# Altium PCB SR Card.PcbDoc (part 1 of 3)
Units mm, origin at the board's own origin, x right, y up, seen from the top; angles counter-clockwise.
Board outline 110.01 x 84.94 mm, 10 copper layers (Top Layer, Layer 2, Layer 3, Layer 4, Layer 5, Layer 6, Layer 7, Layer 8, Layer 9, Bottom Layer), stack 2.452 mm thick; 165 components, 84 nets, 582 pads, 1965 vias.
Unrouted connection lines stored in the file: 24.
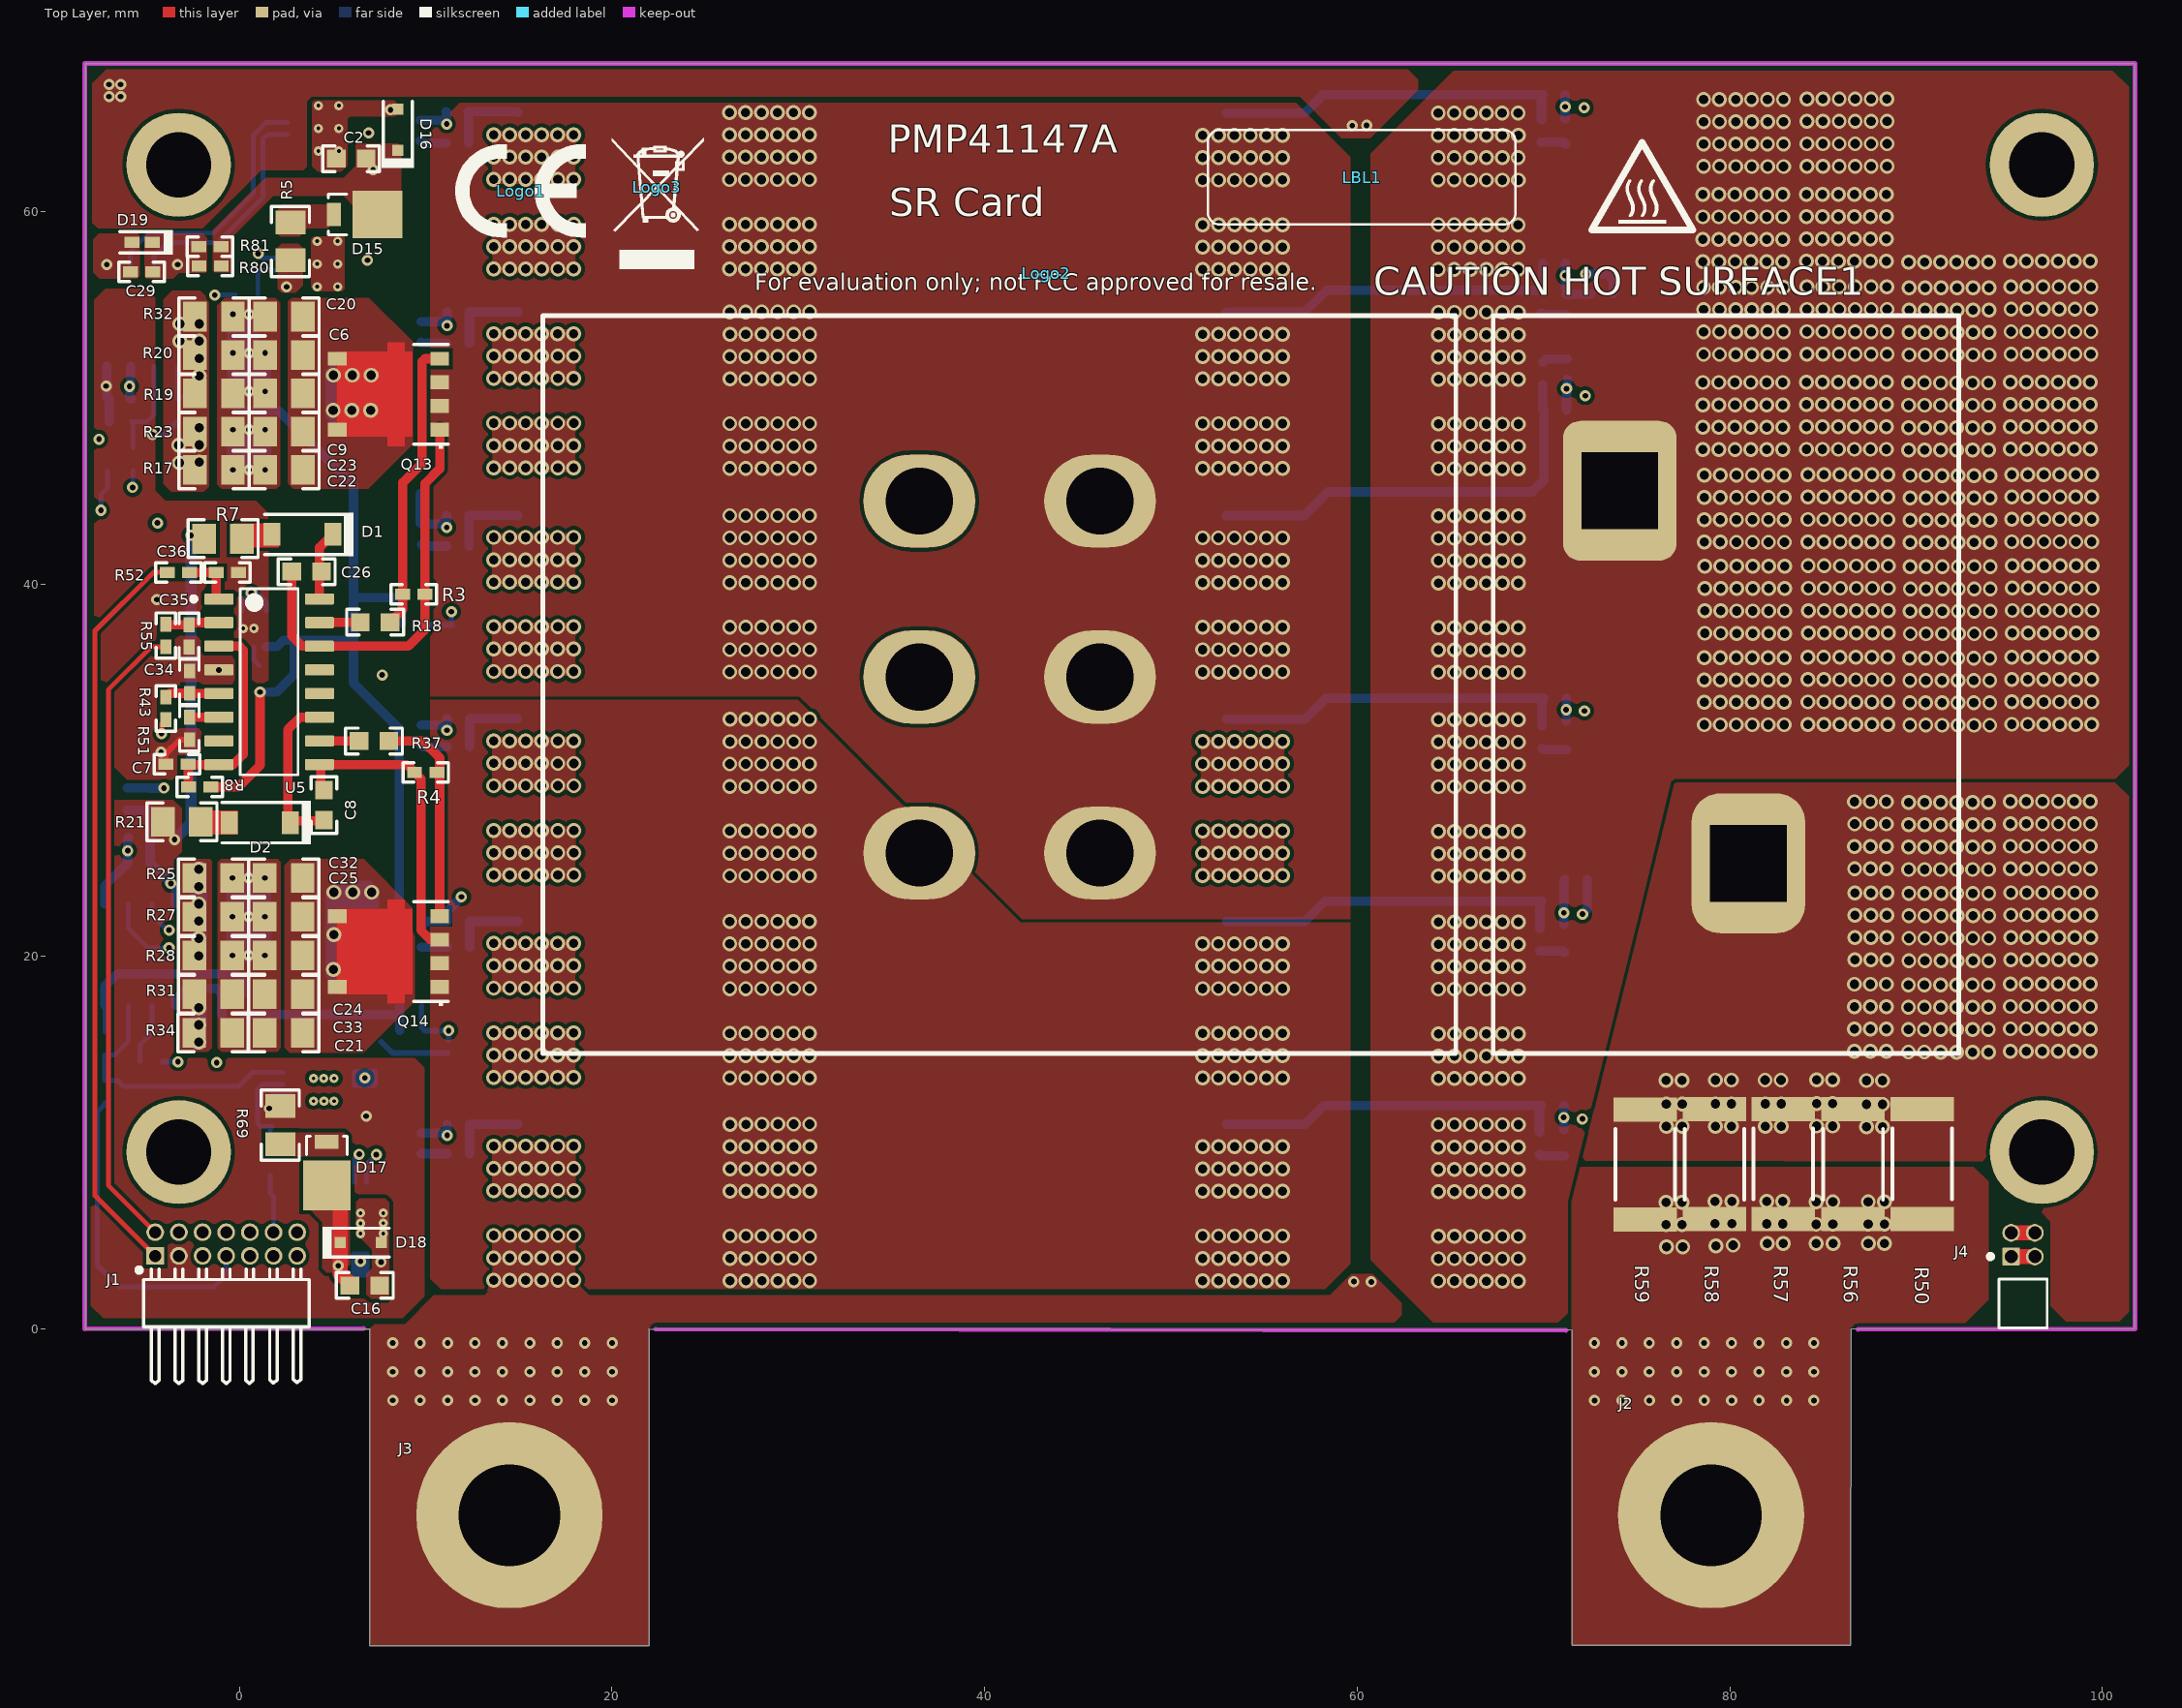
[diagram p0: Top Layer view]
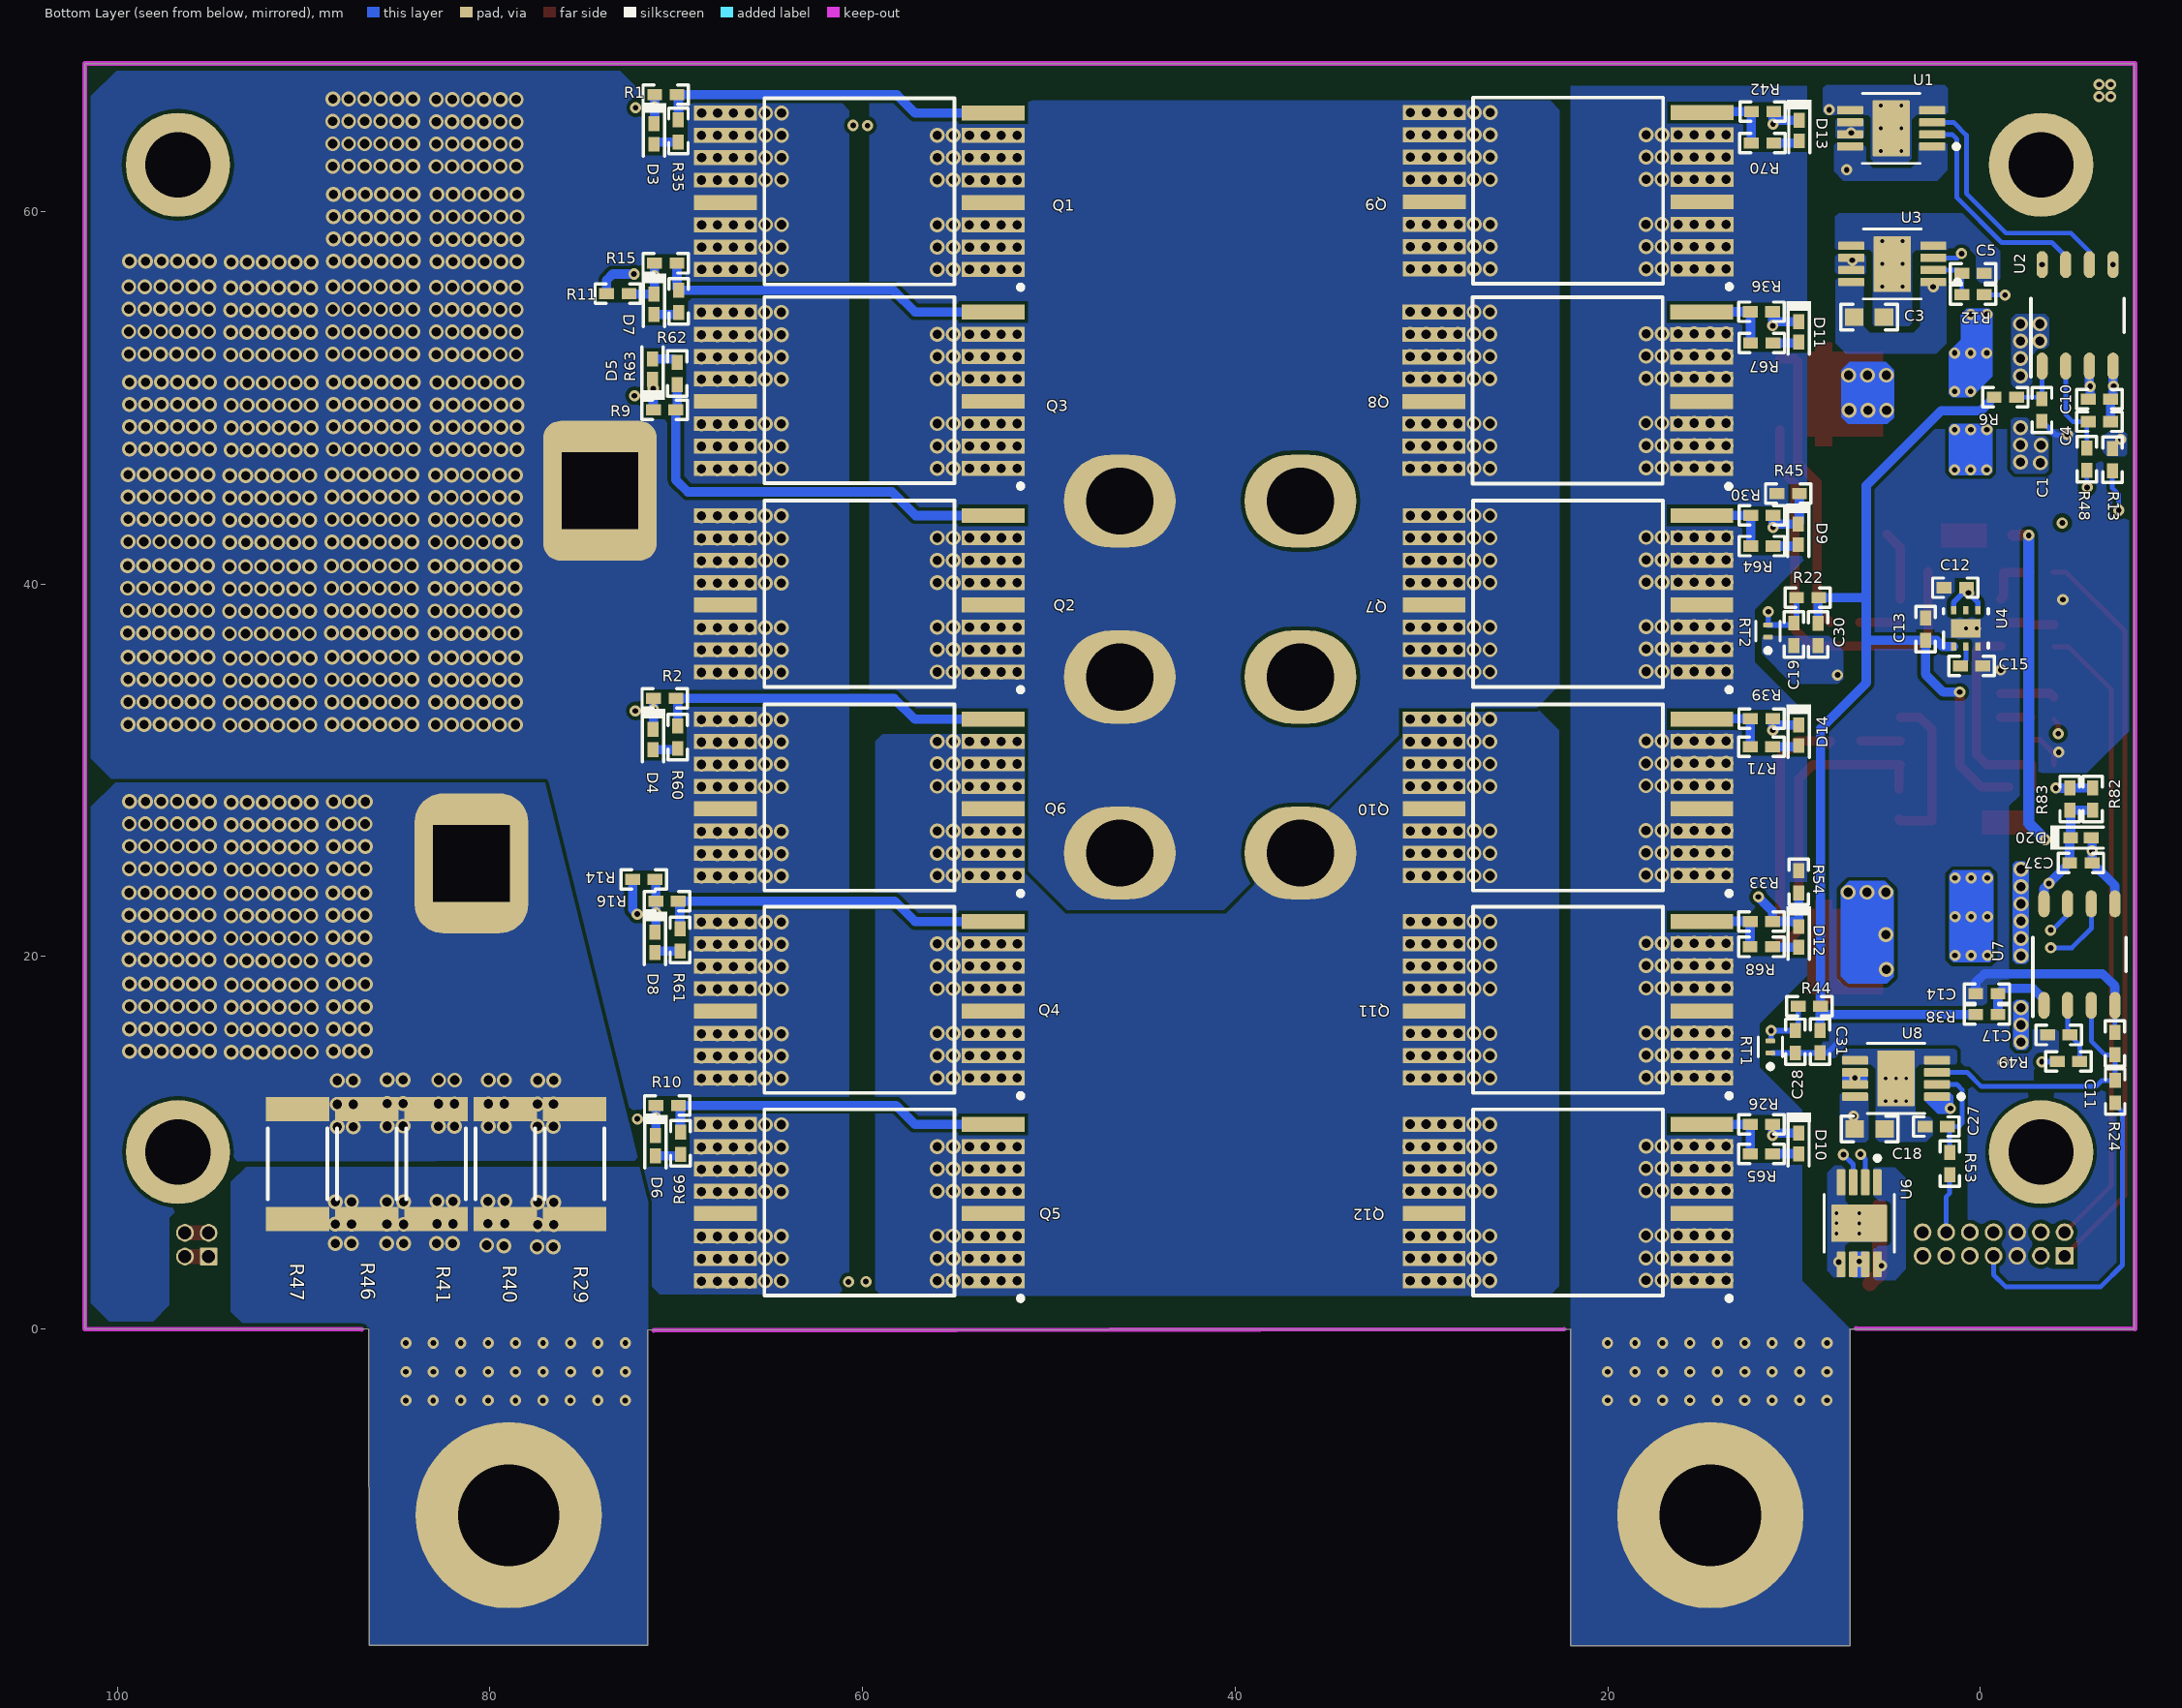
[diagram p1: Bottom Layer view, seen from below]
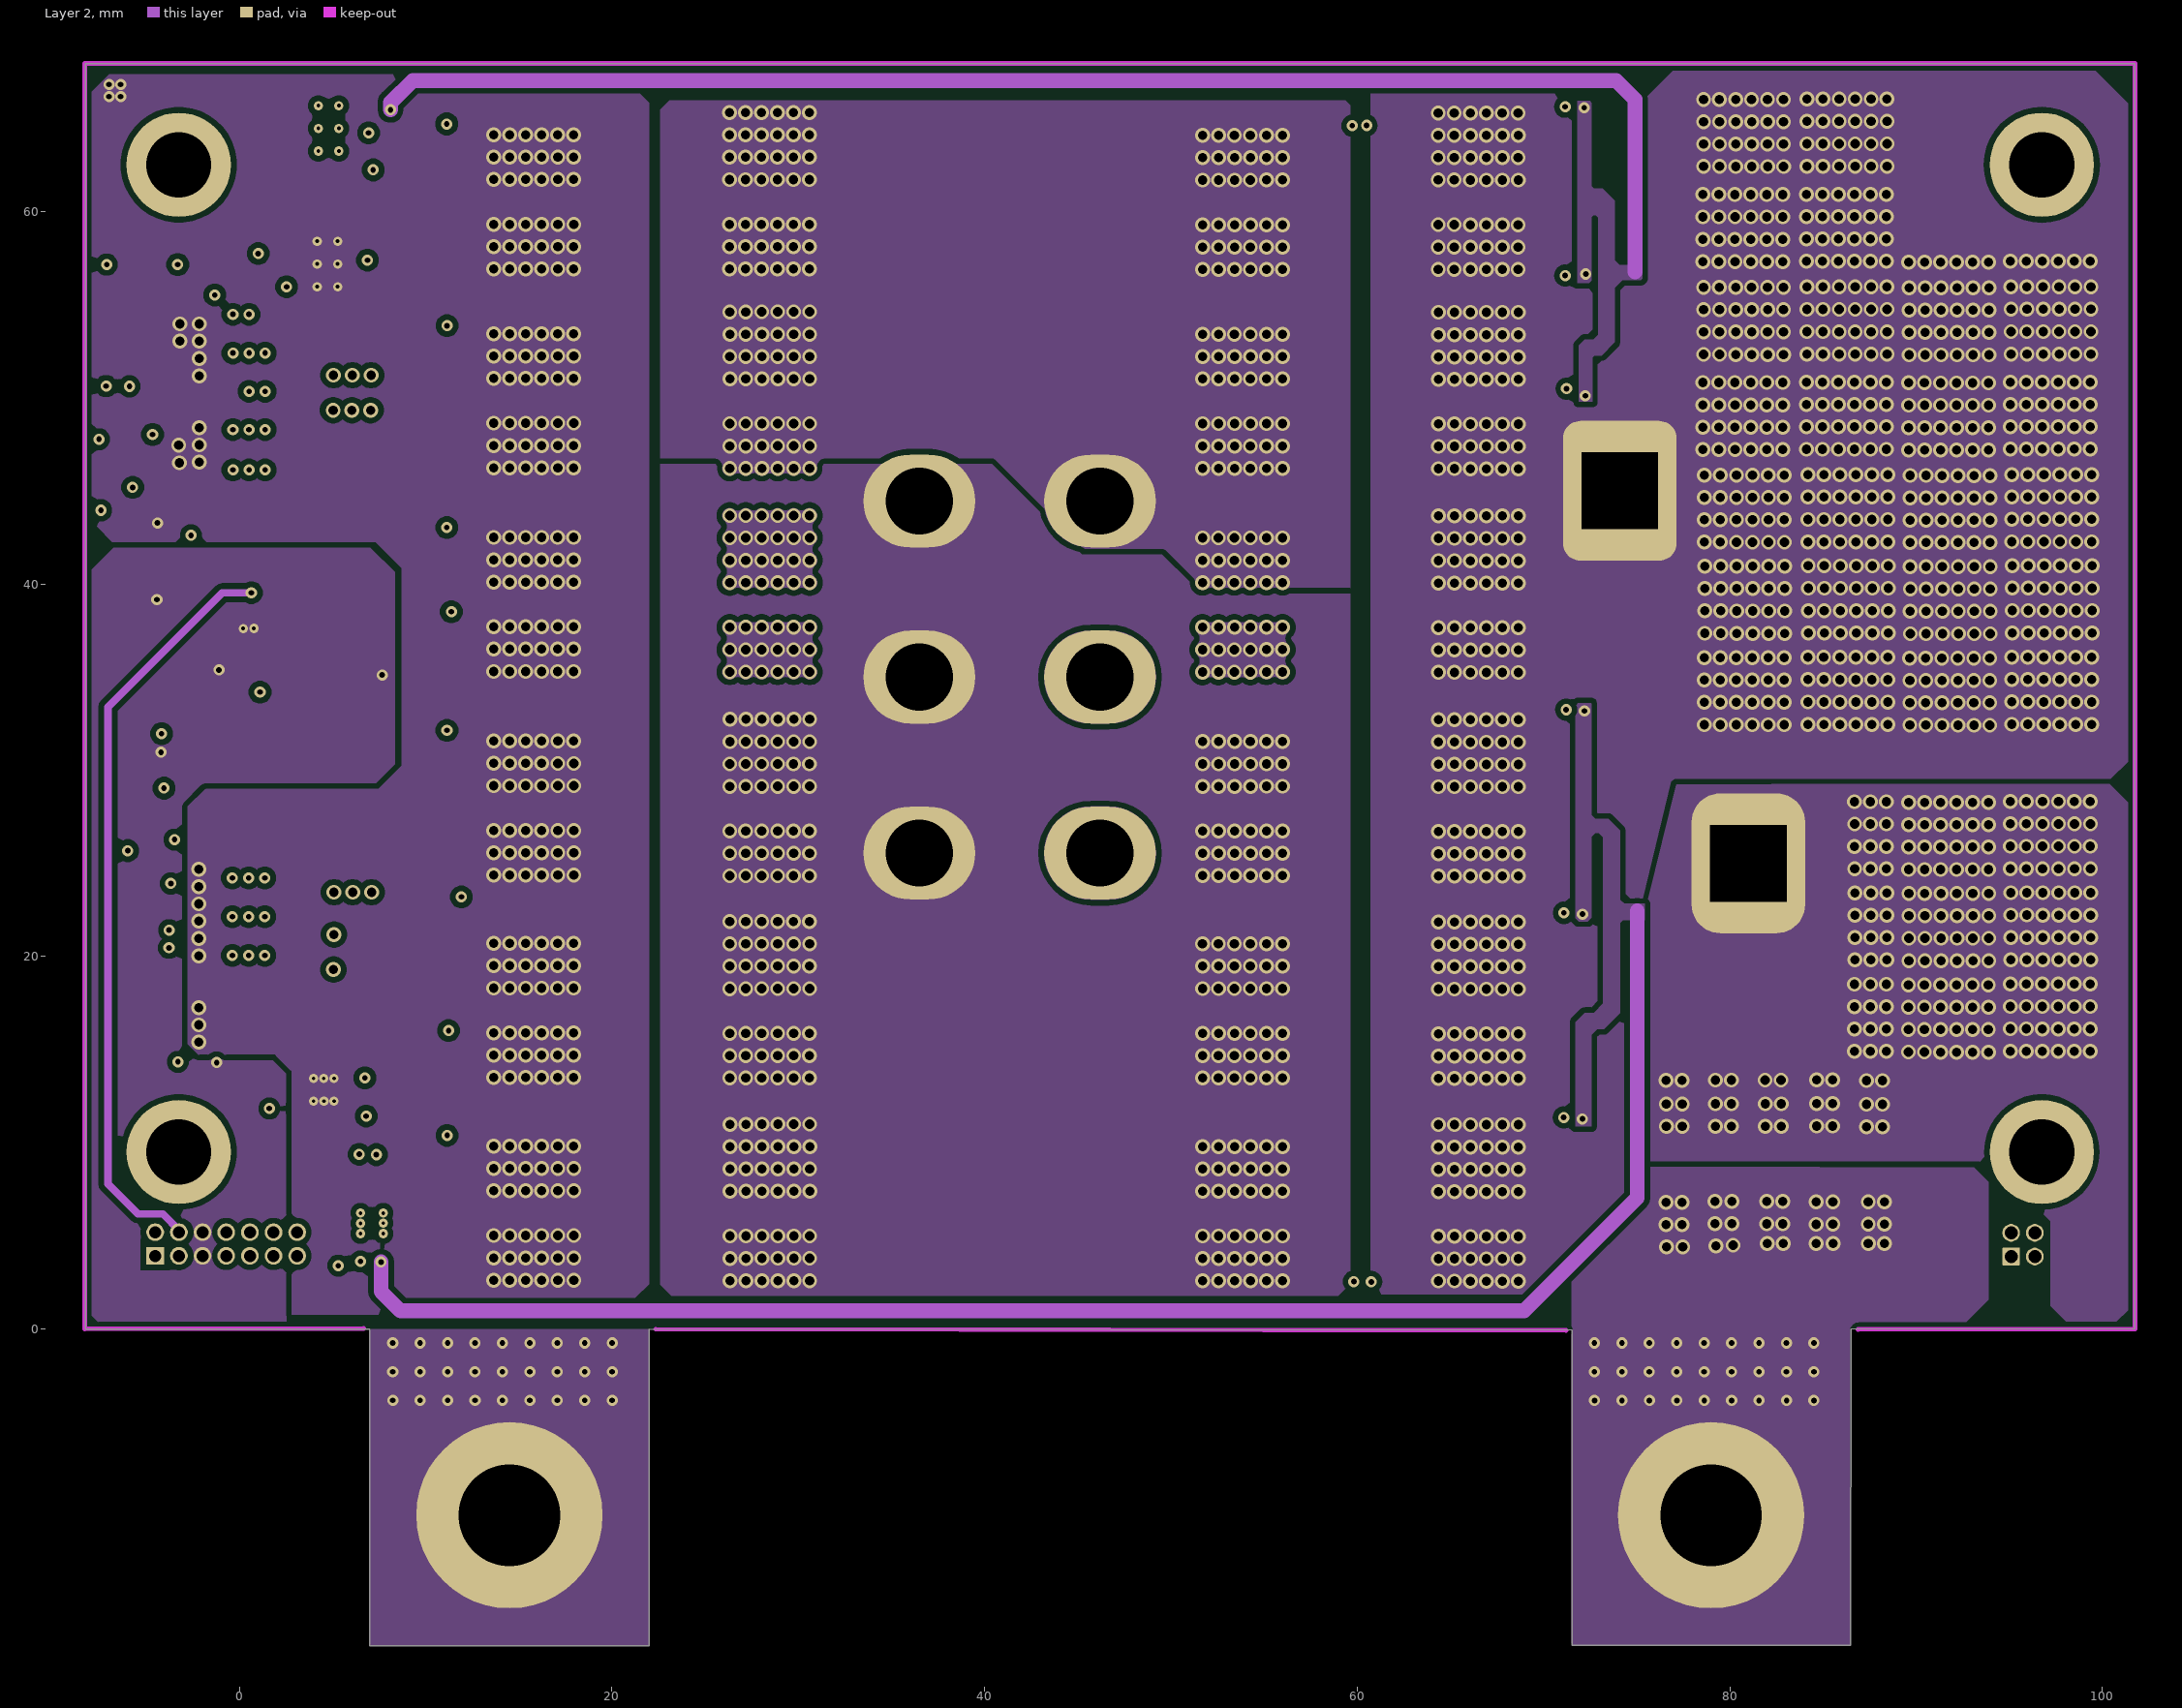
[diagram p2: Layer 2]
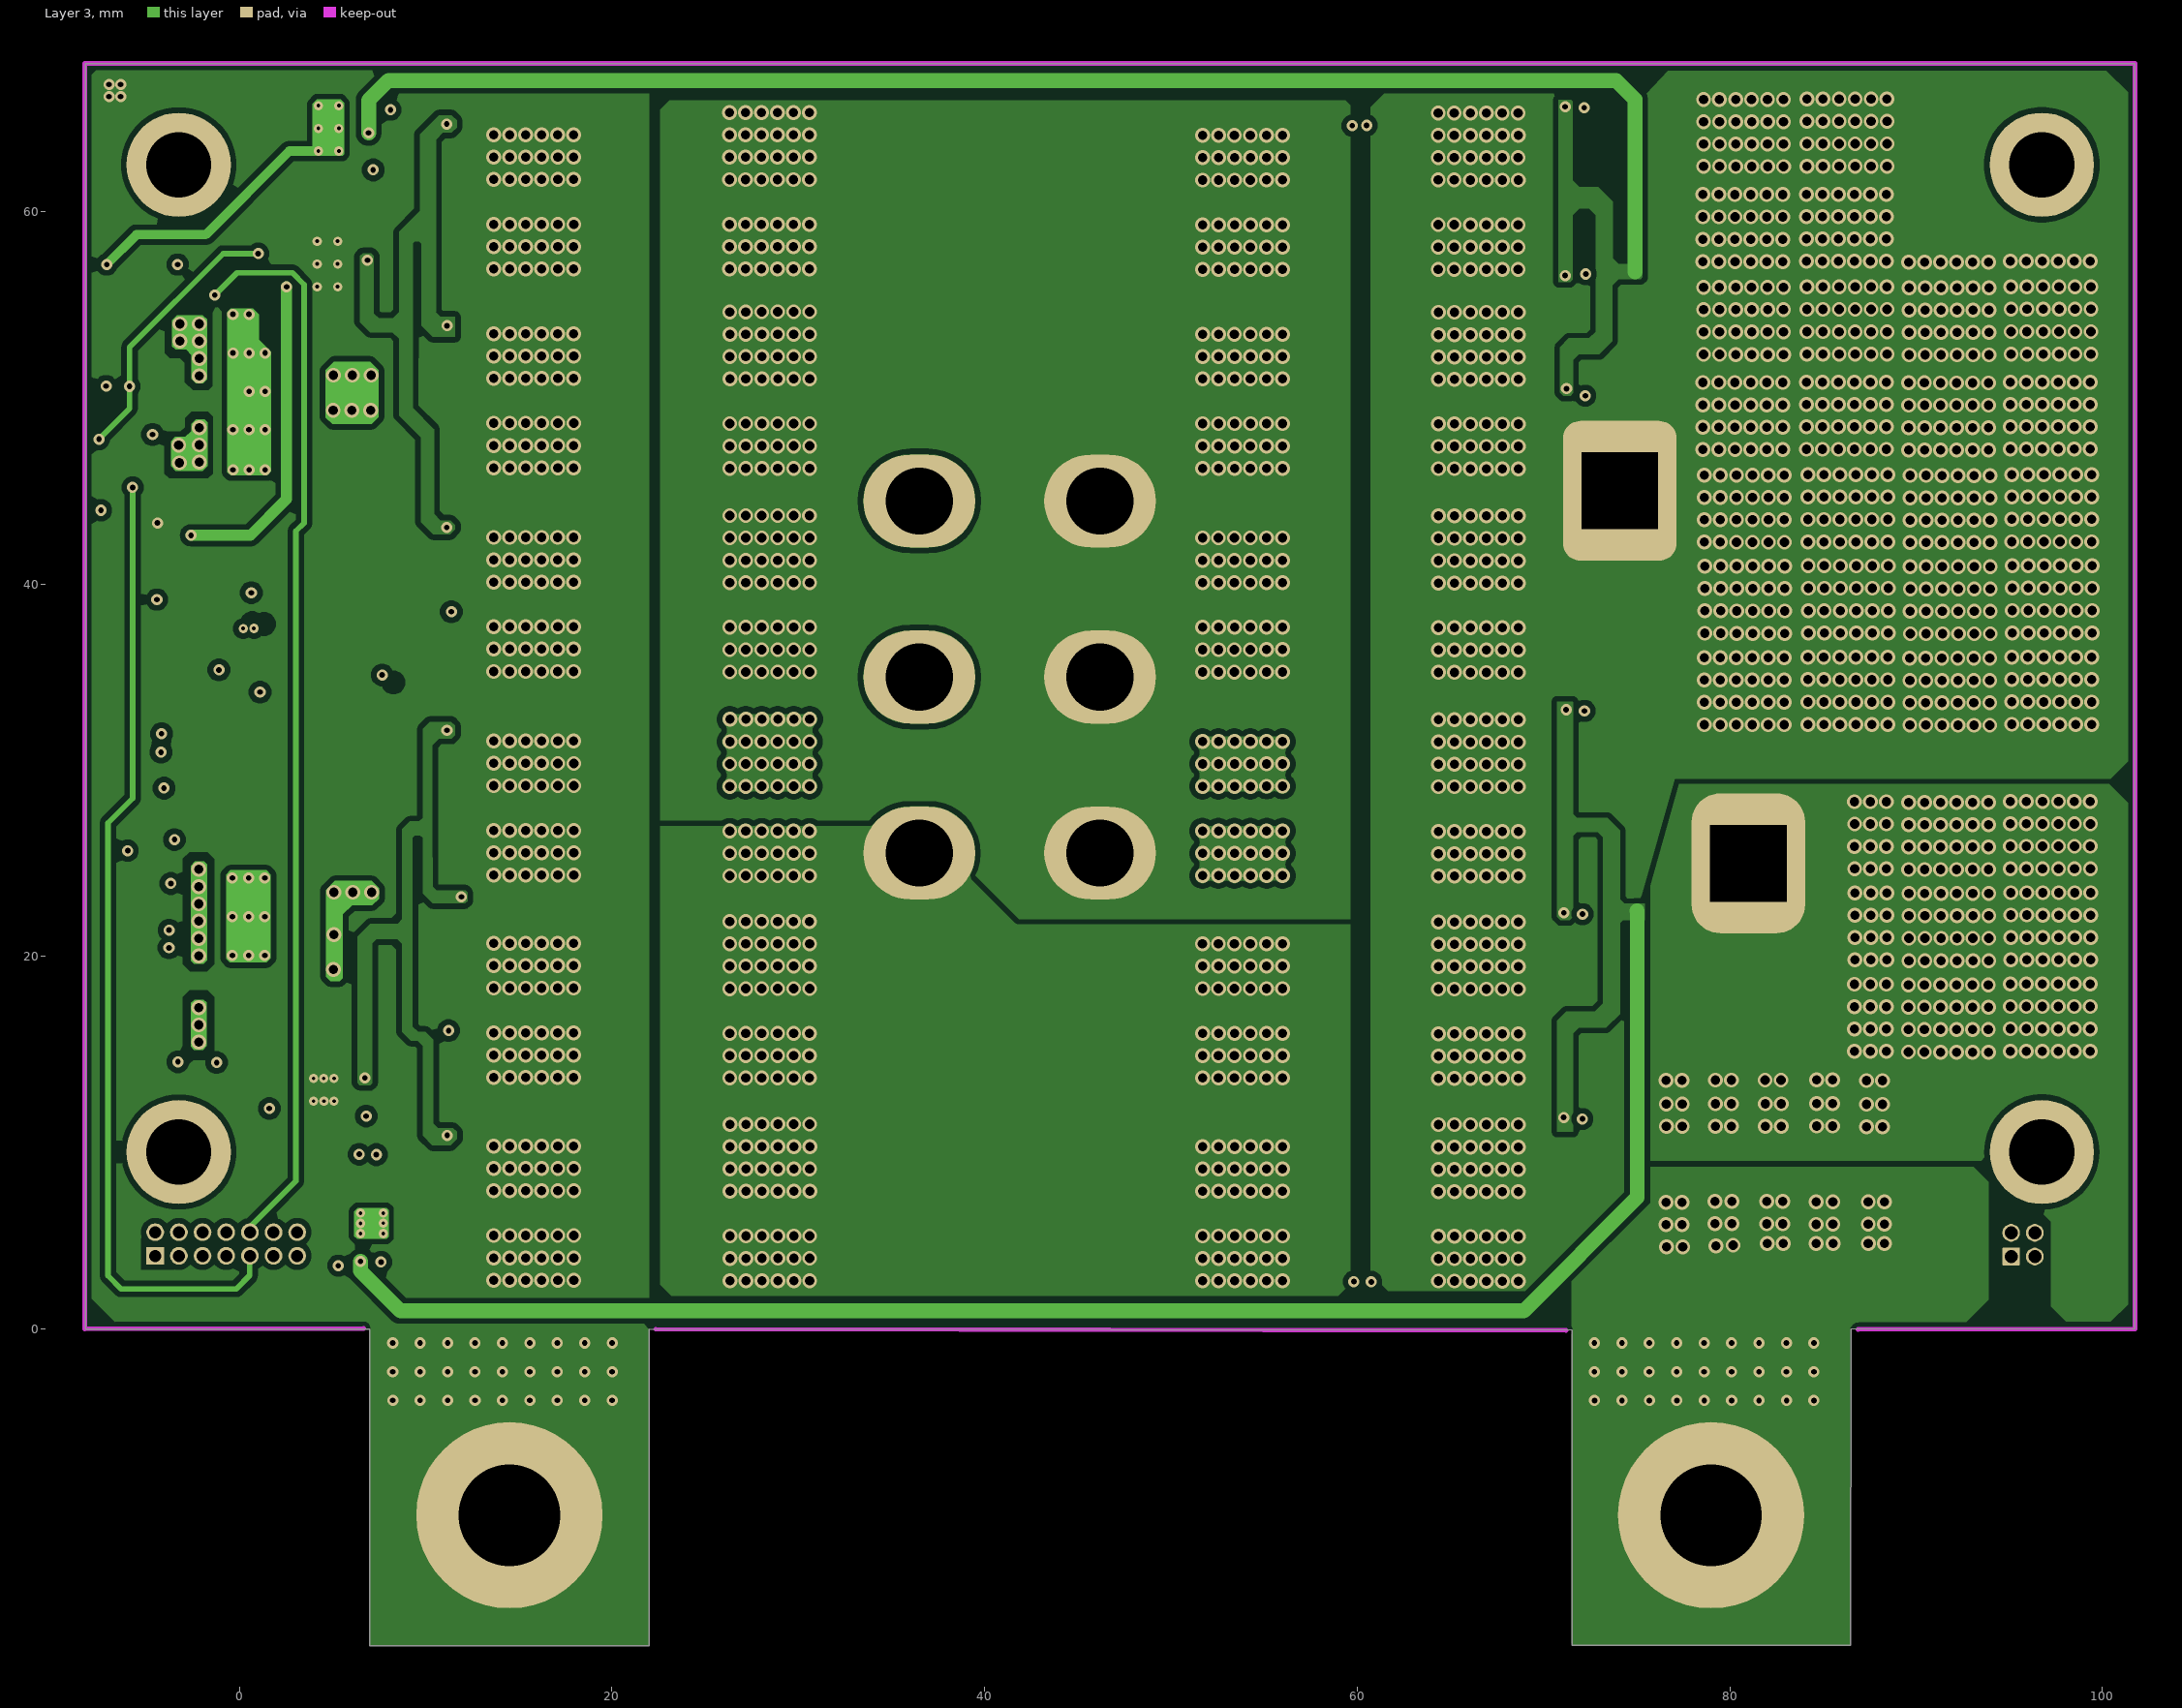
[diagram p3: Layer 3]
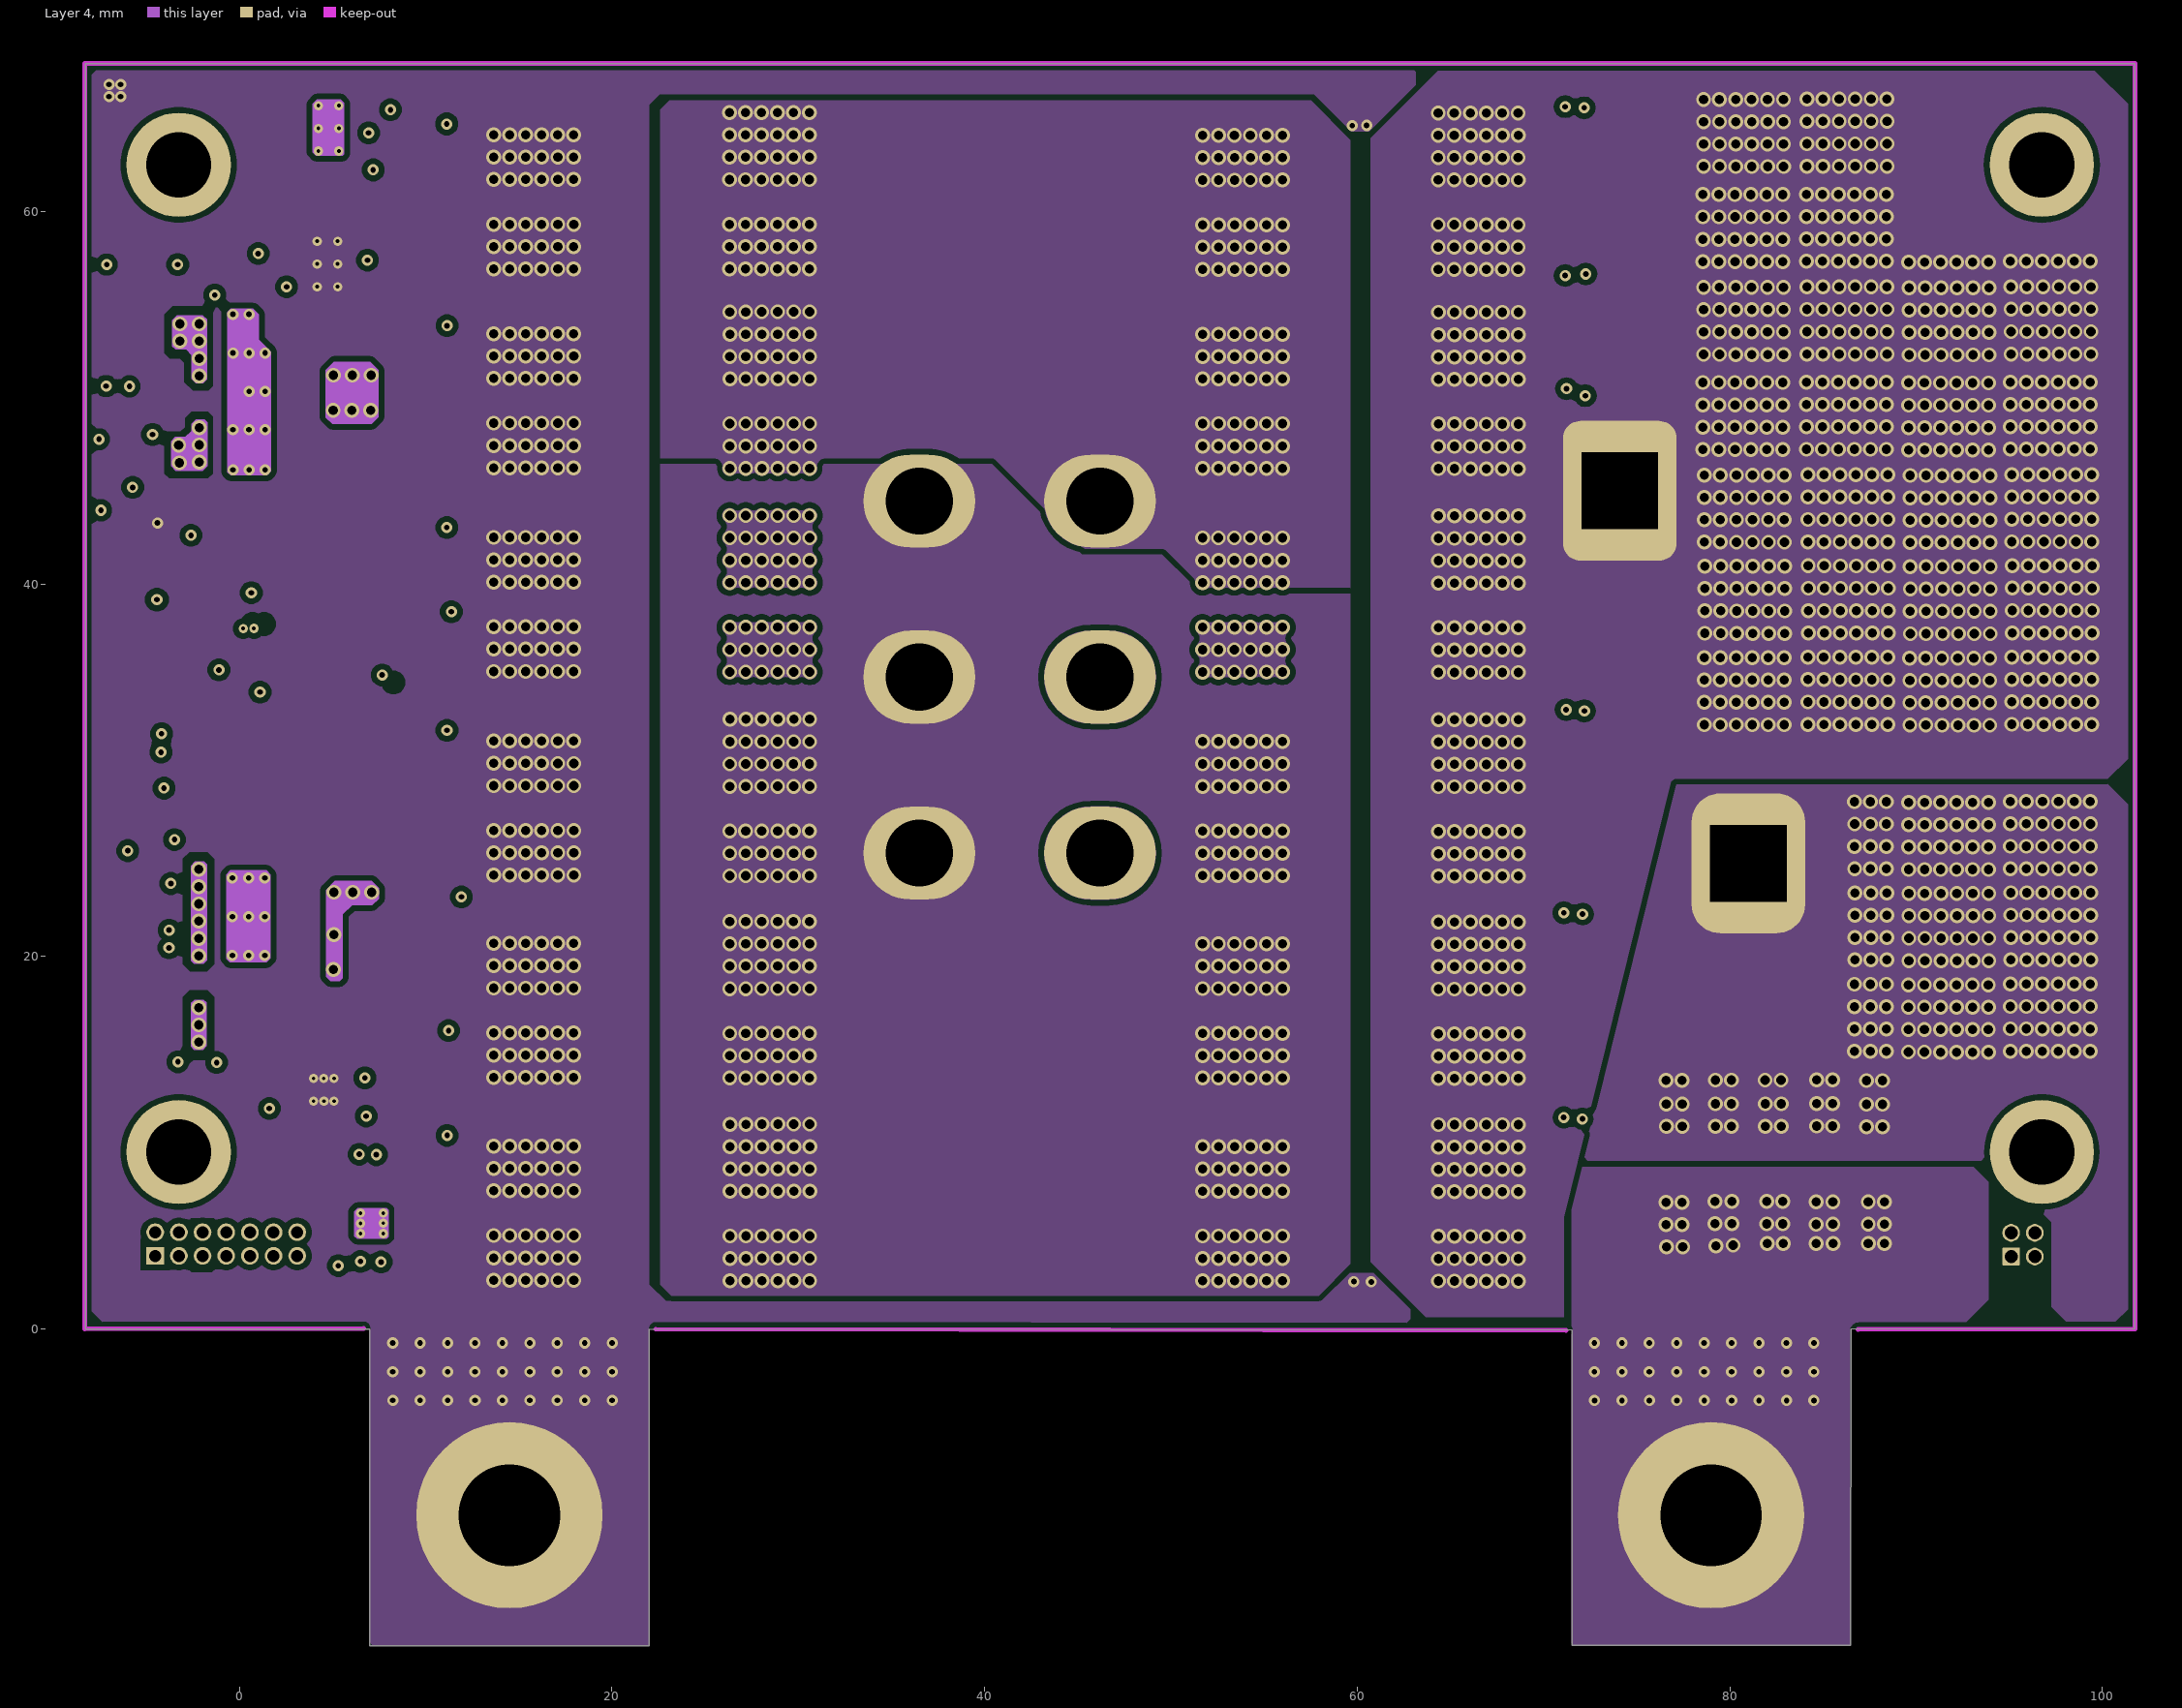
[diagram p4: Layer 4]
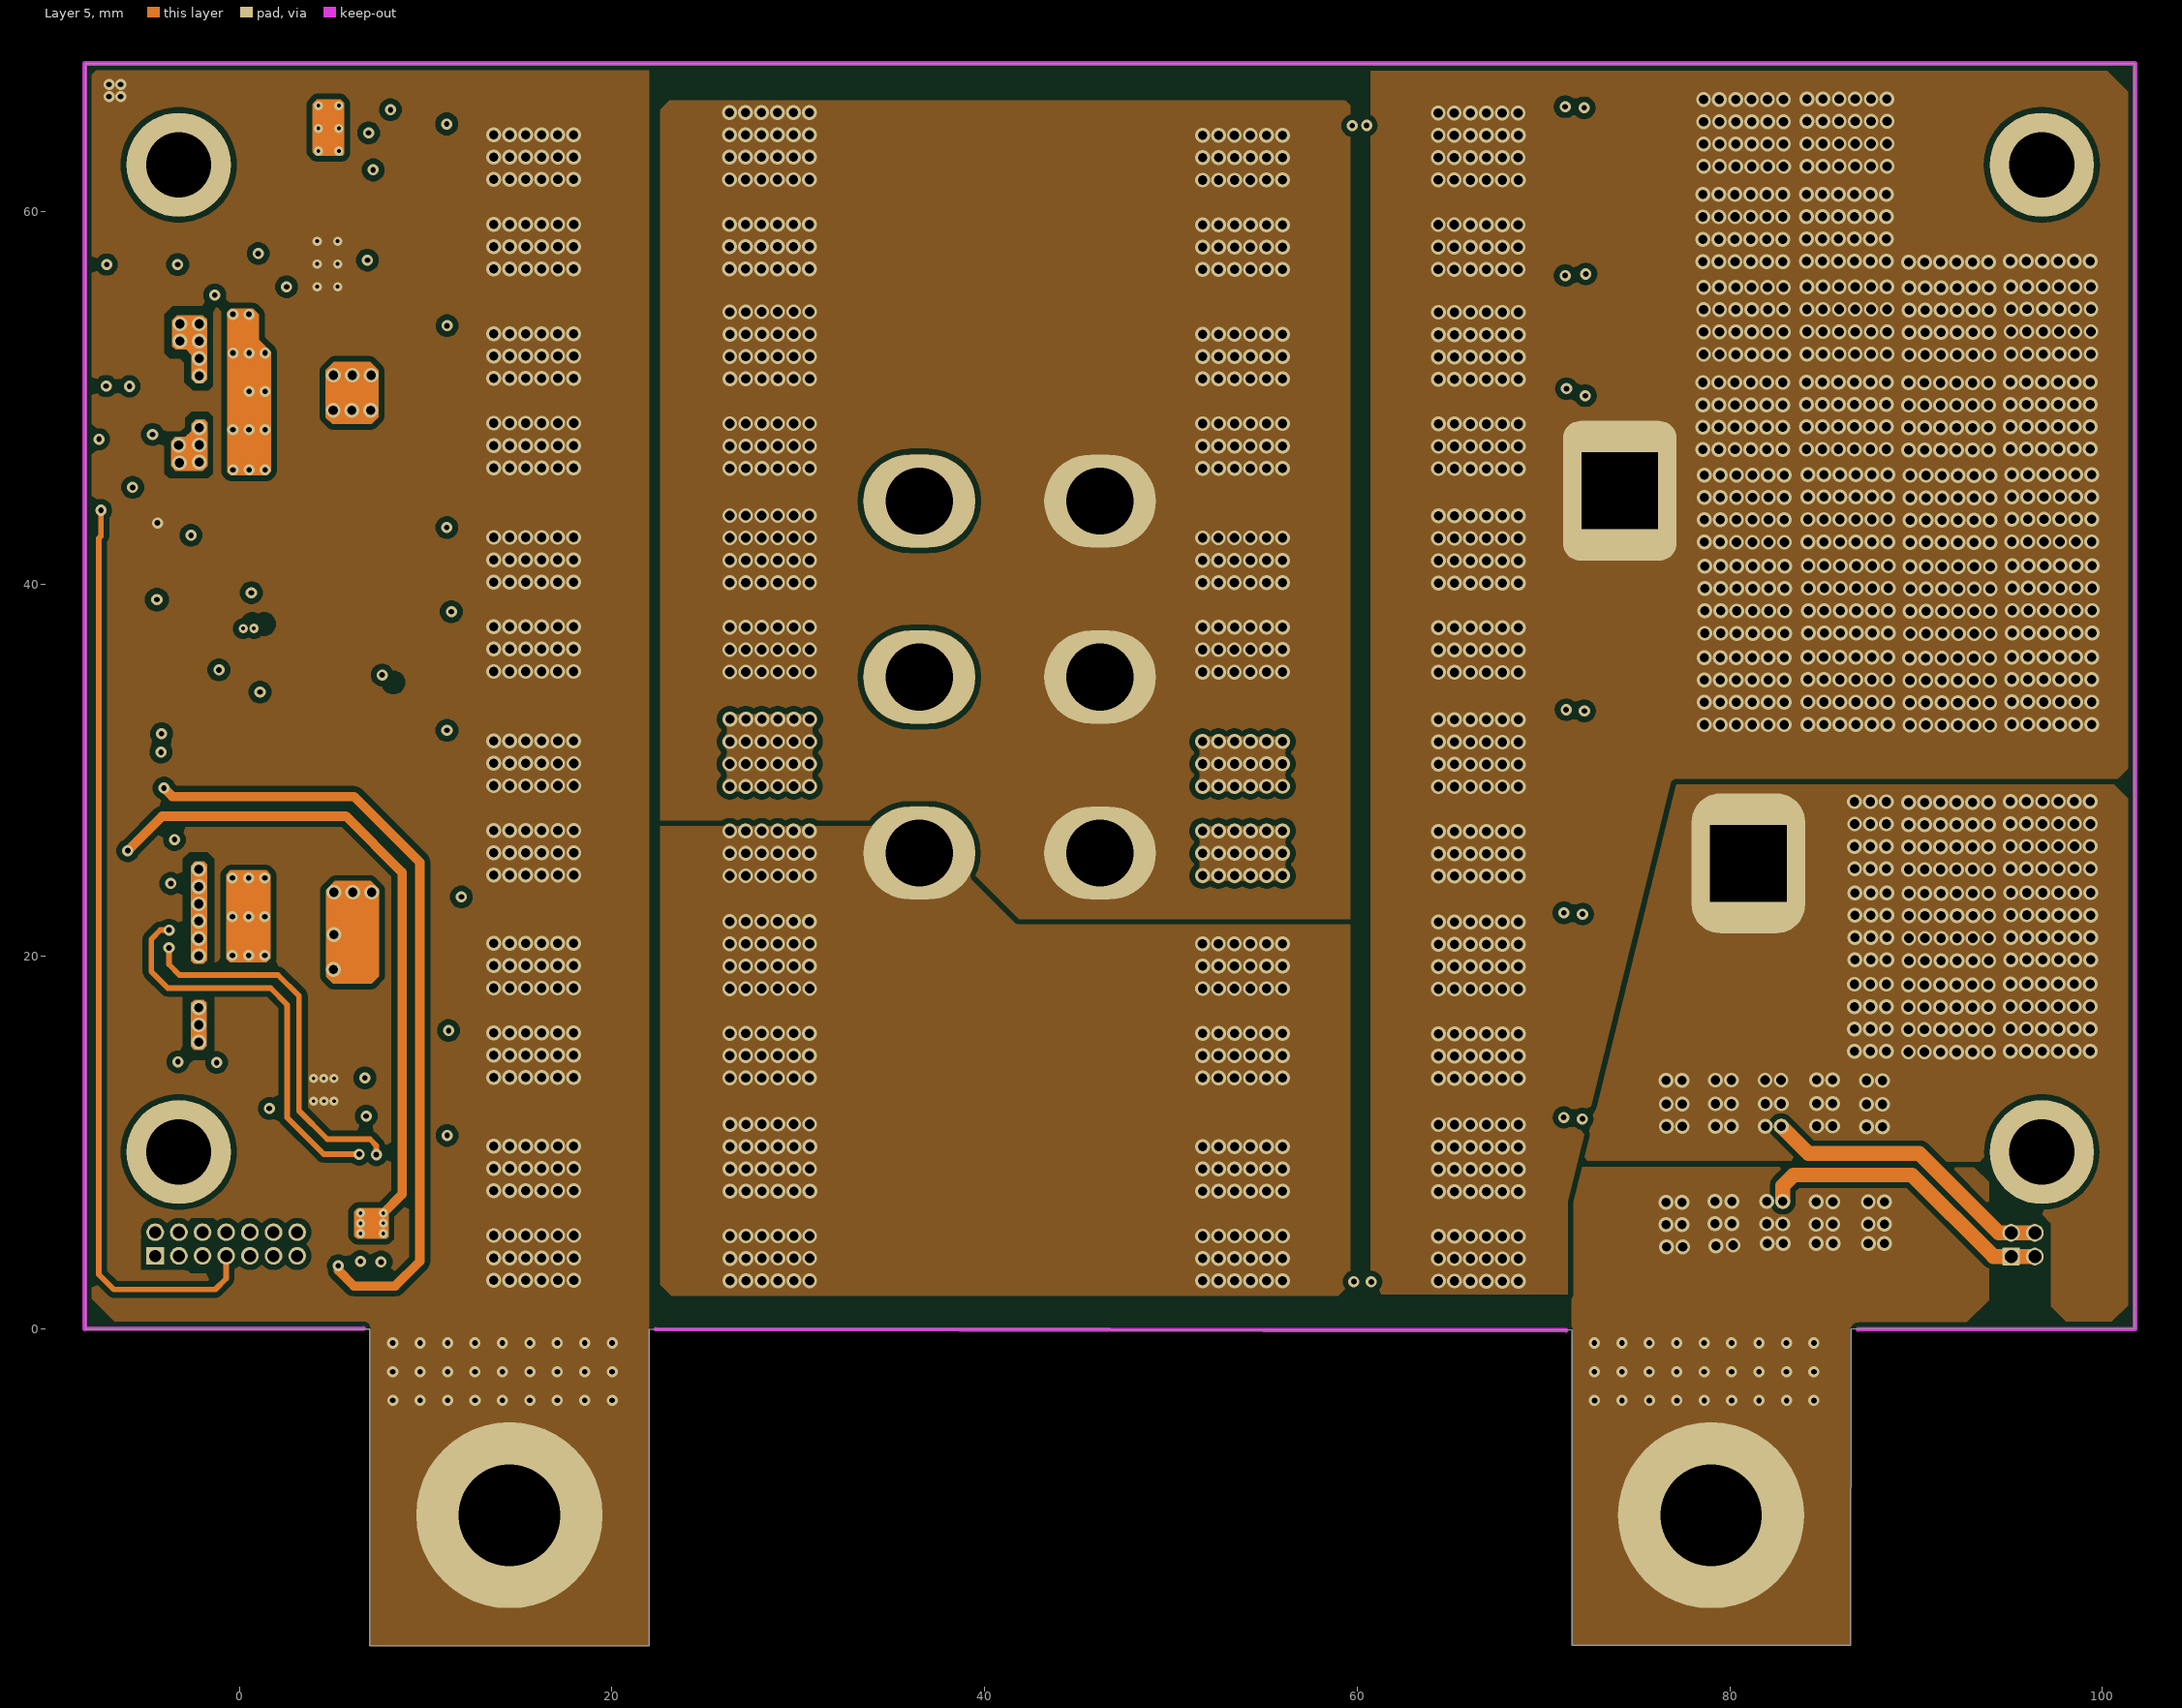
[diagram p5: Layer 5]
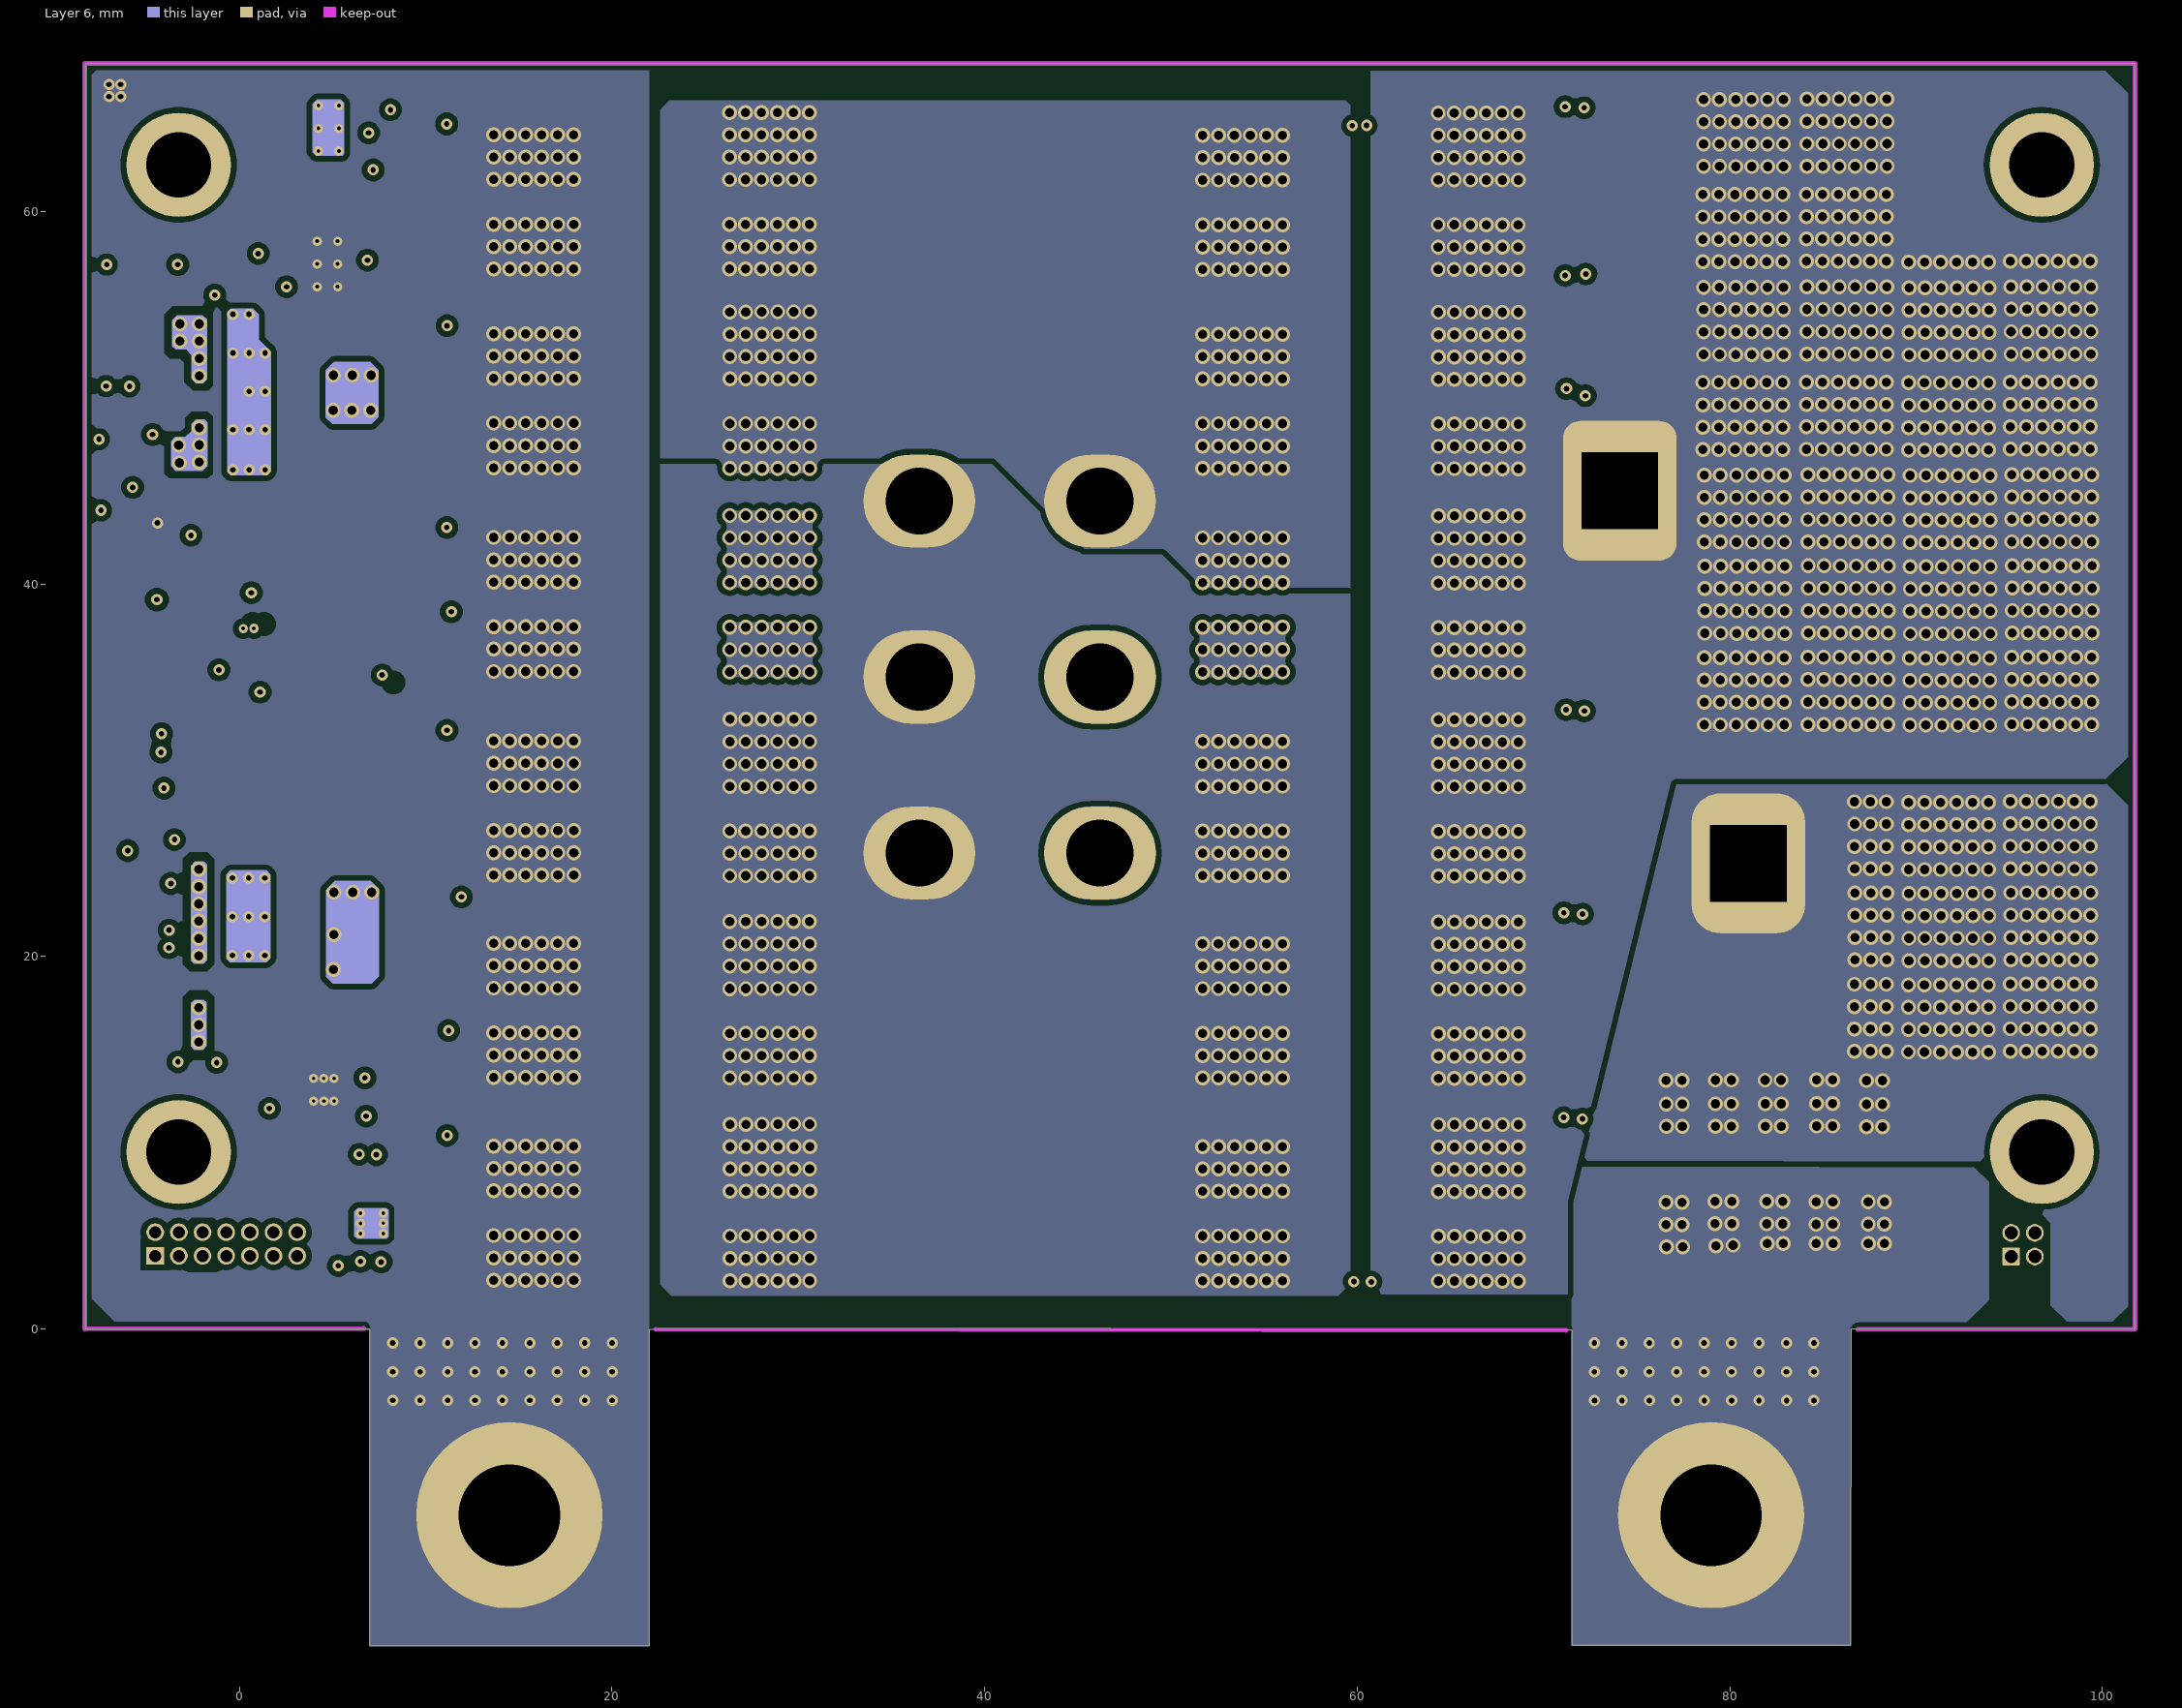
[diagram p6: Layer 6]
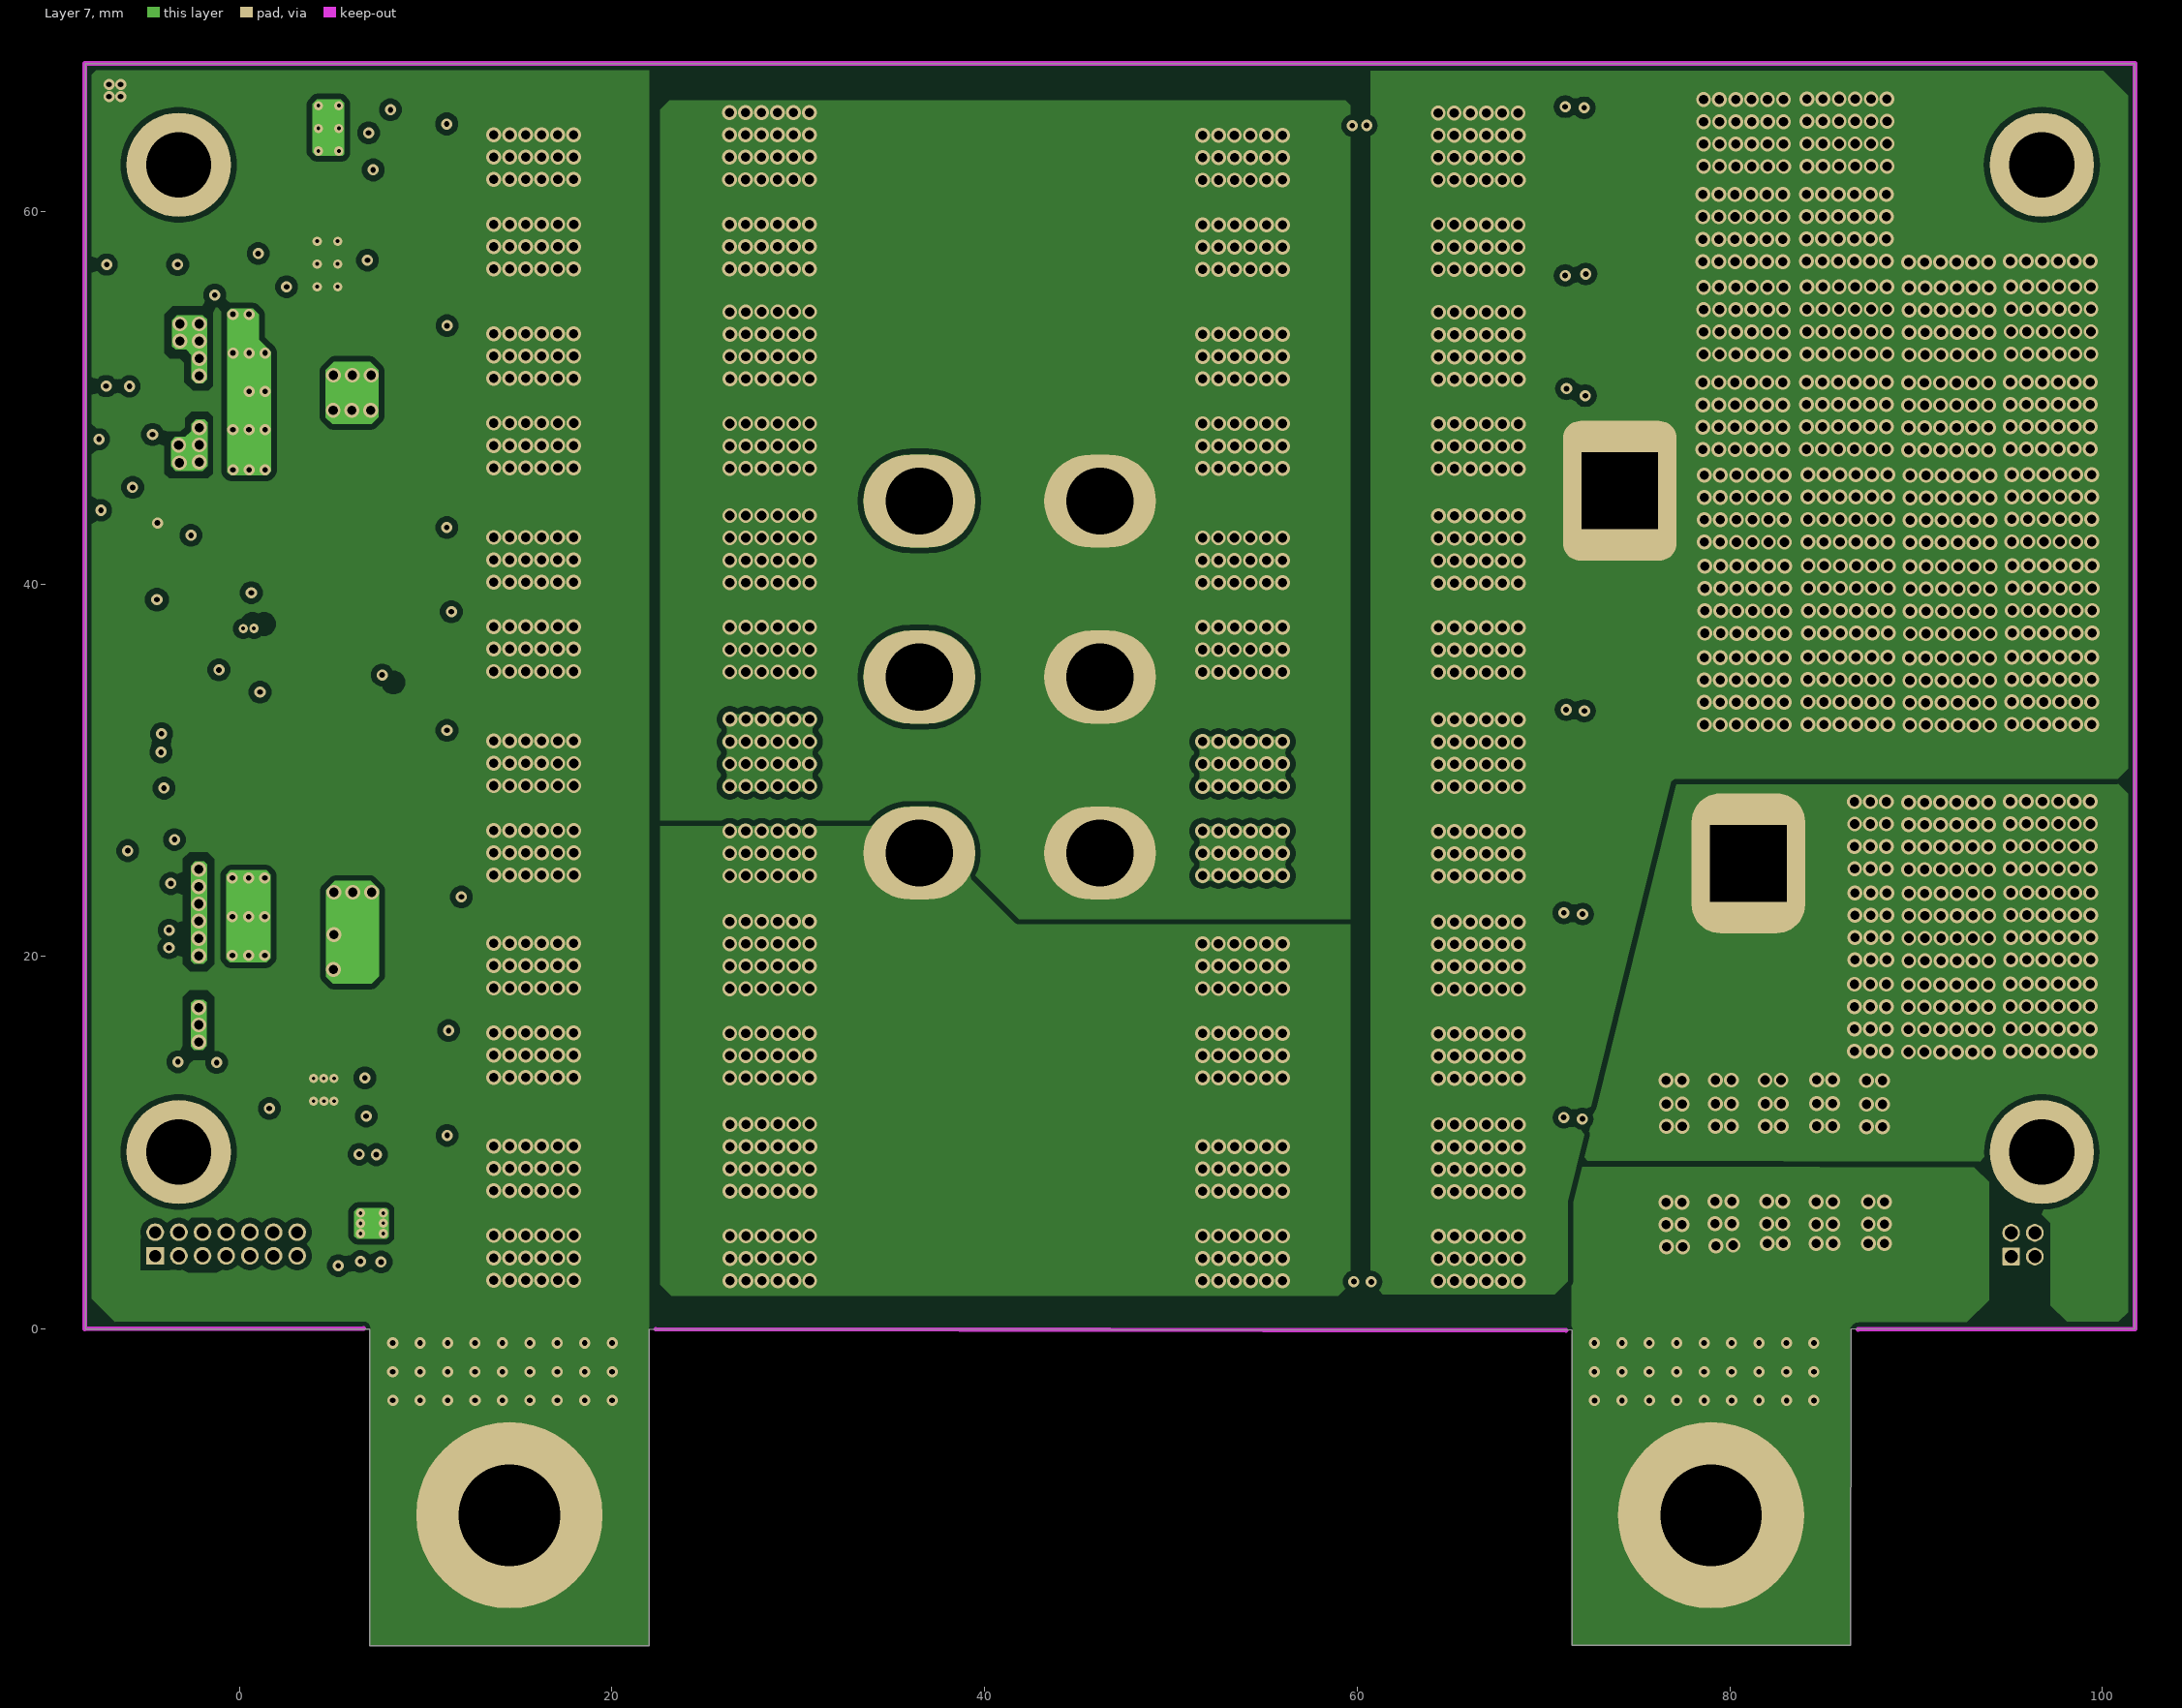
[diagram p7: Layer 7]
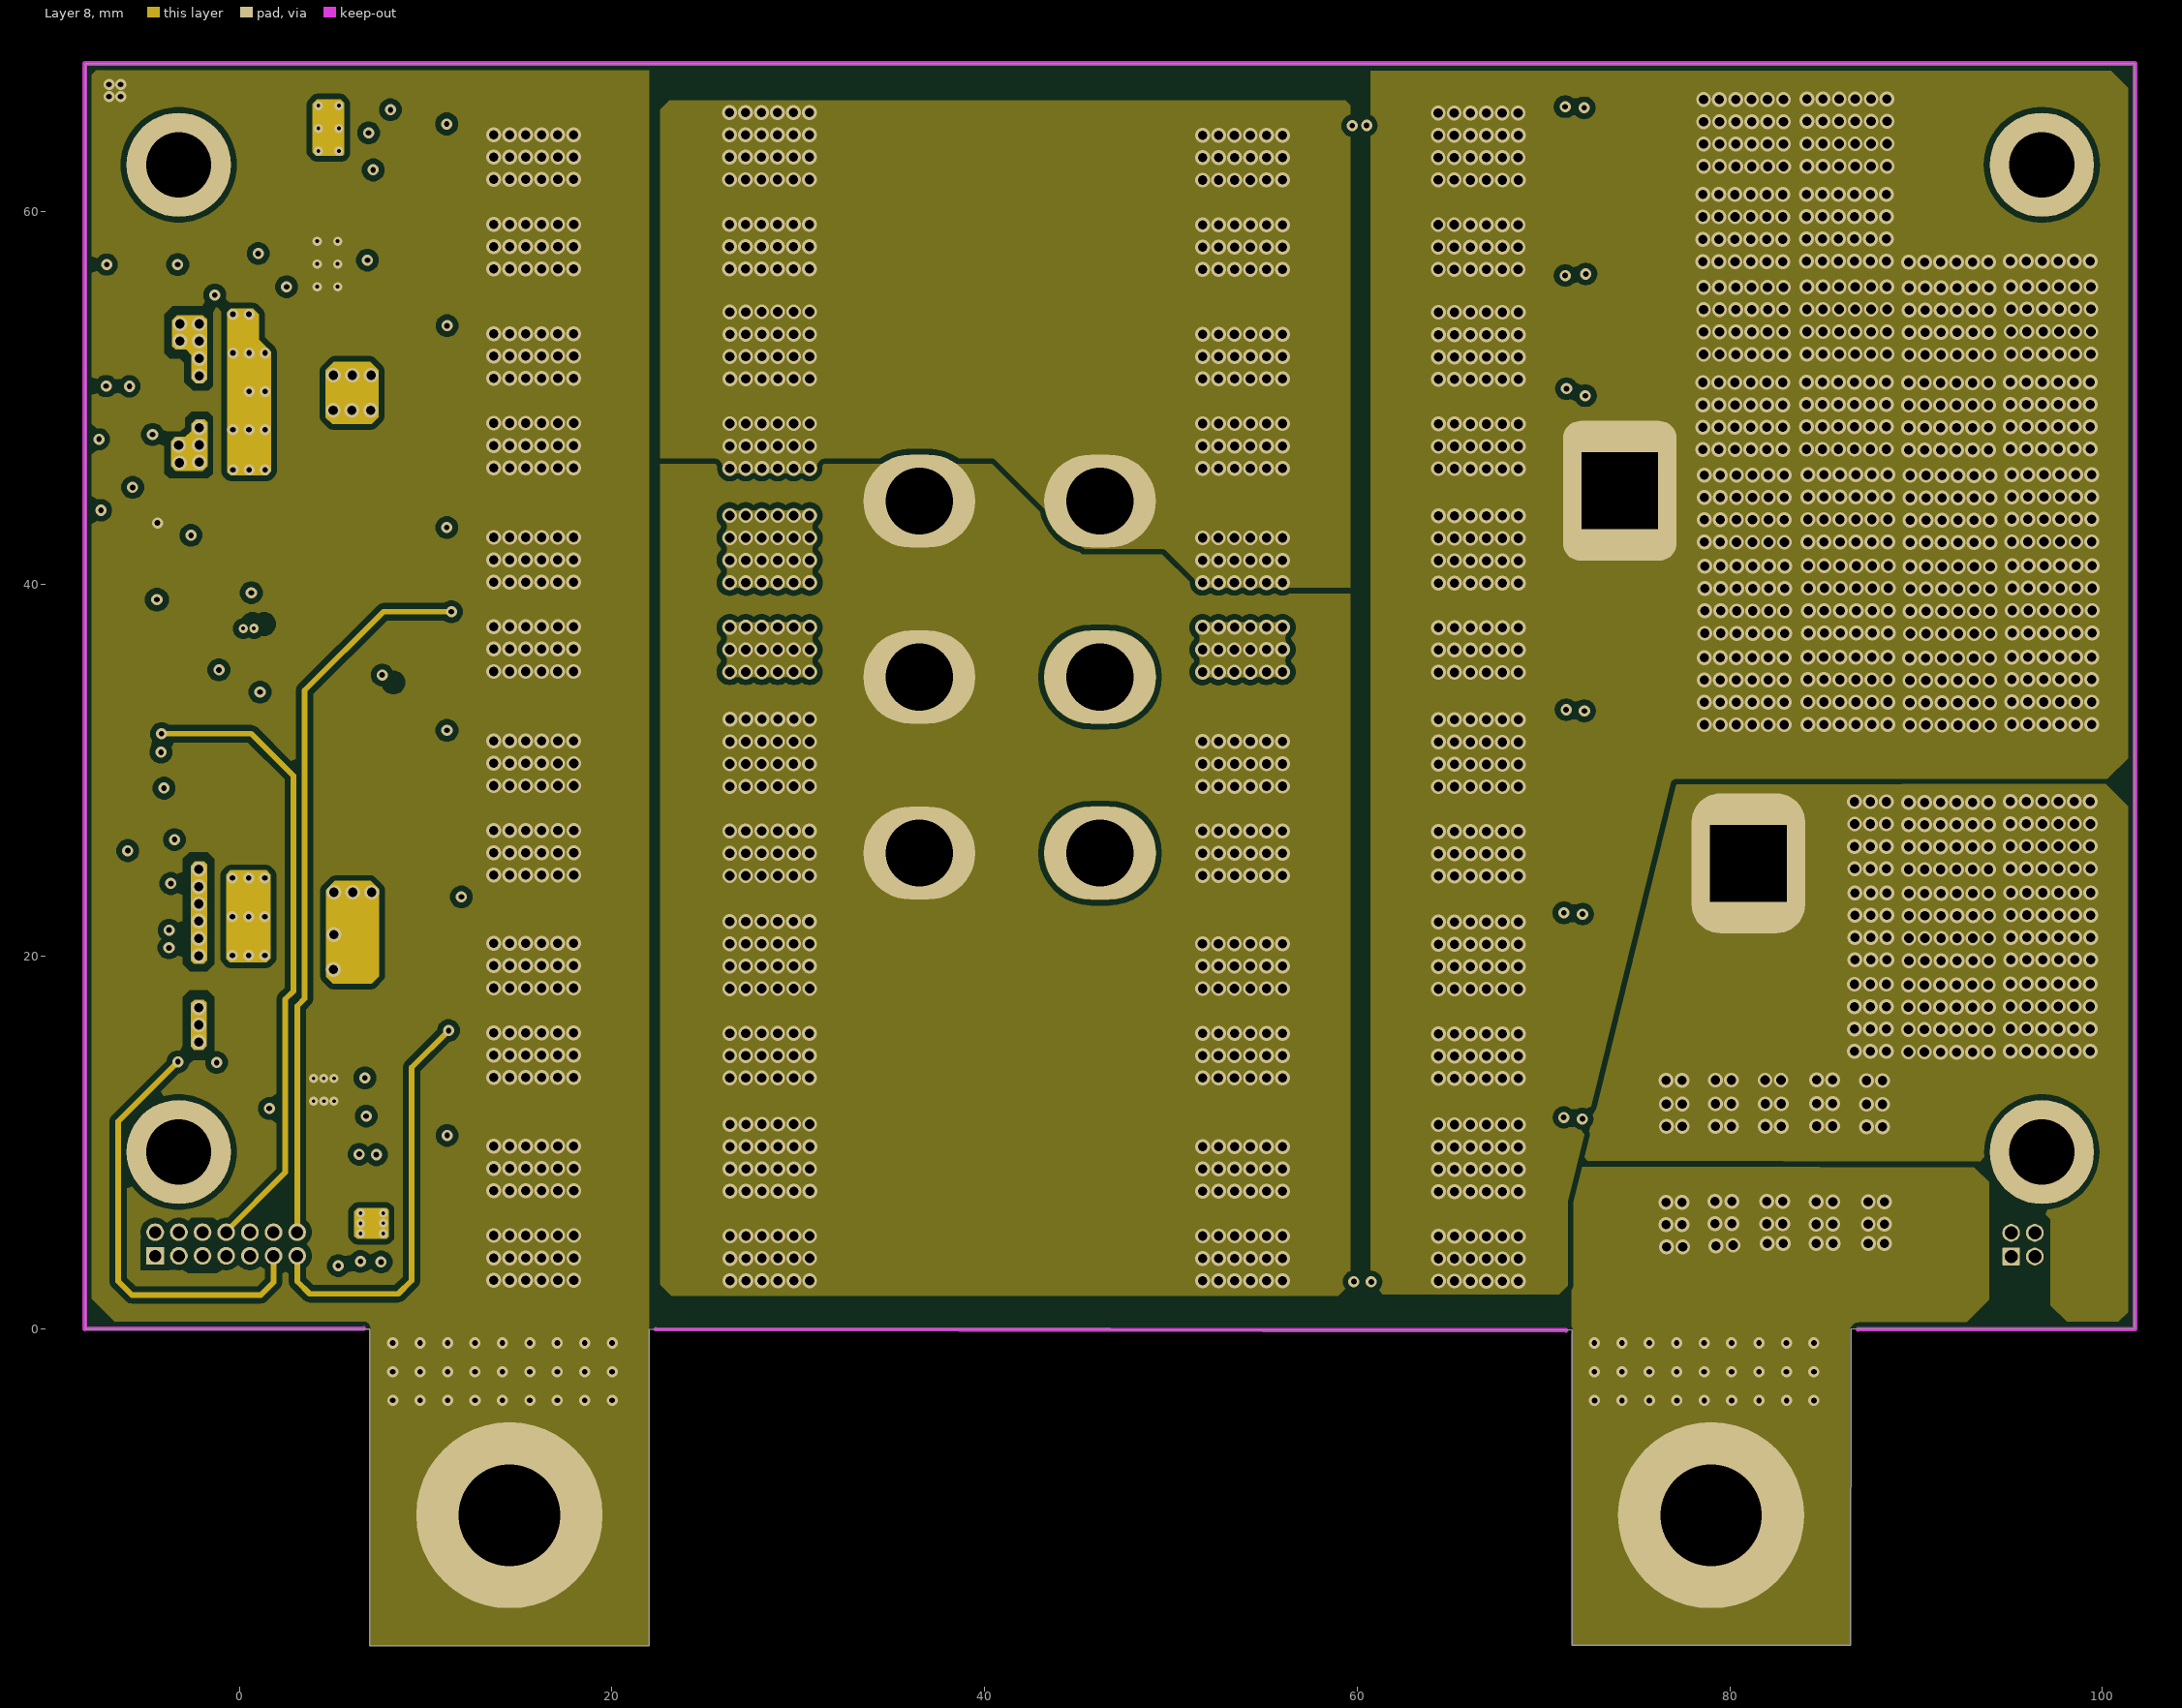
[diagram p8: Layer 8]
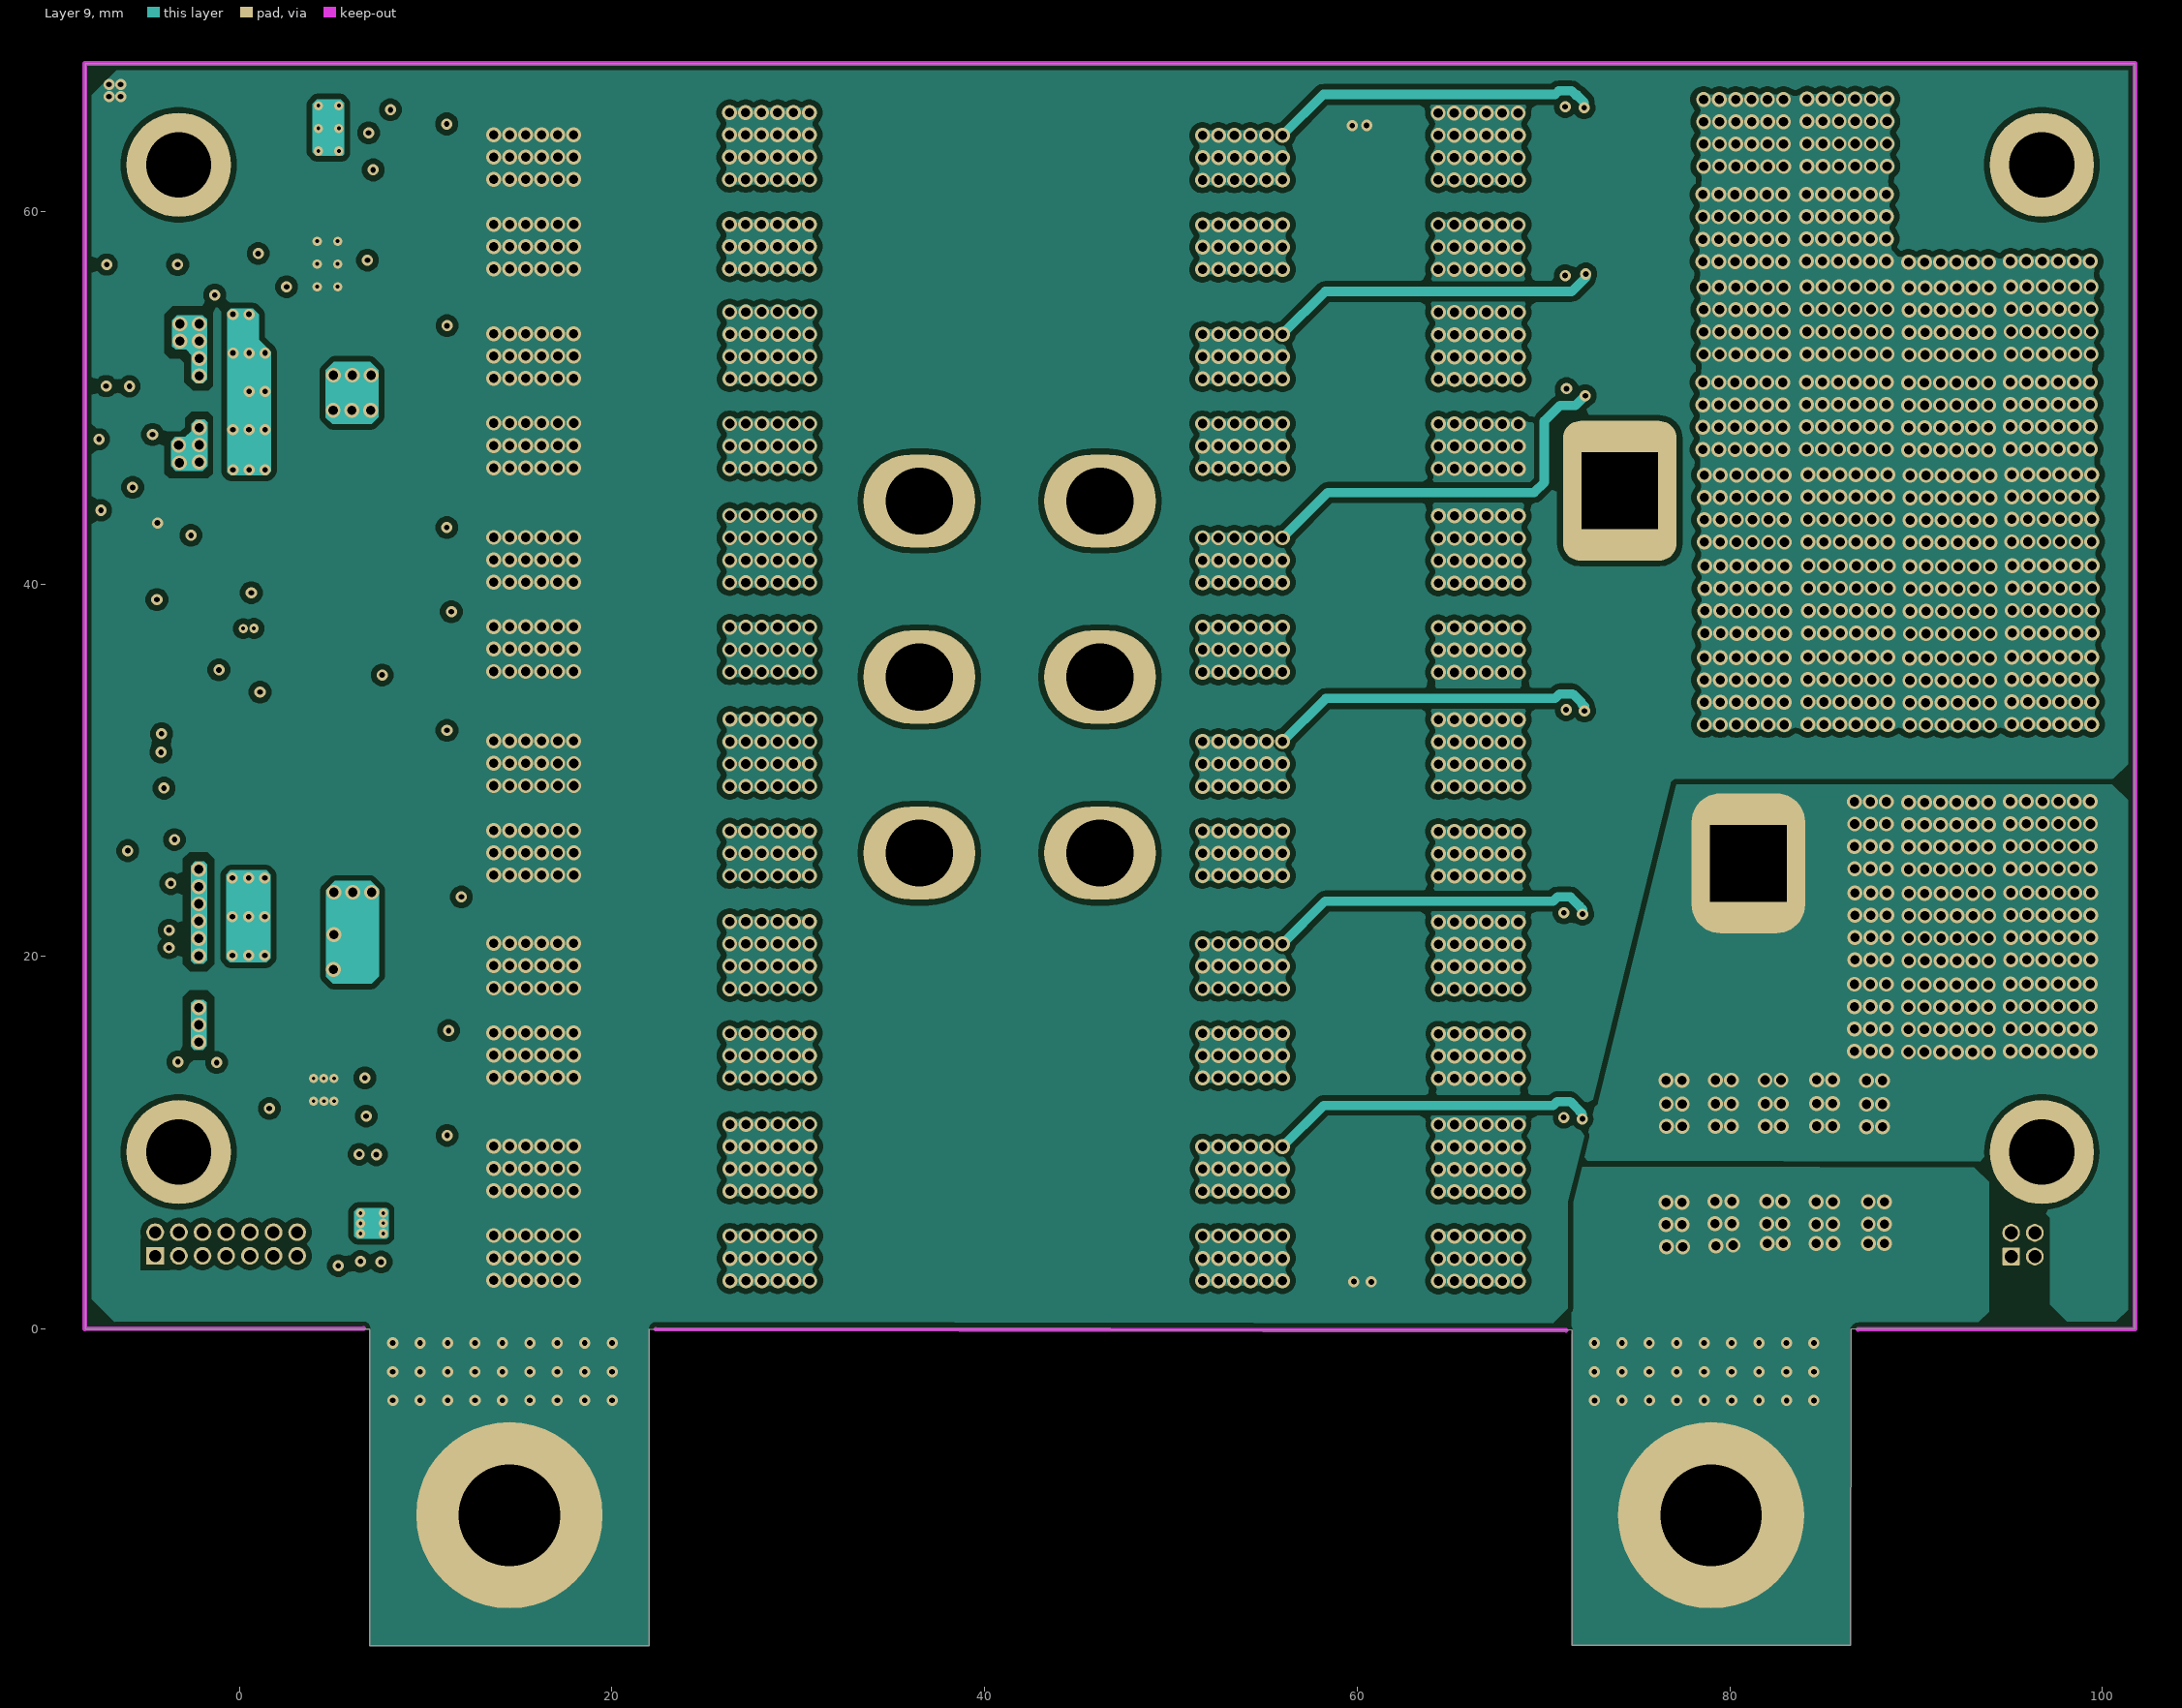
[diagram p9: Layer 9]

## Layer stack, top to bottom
Top Solder: solder mask 0.0102, Solder Resist, Dk 3.5
Top Layer: signal copper 0.07
Dielectric 5: prepreg 0.15, PP-006, Dk 4.1
Layer 2: signal copper 0.14
Dielectric 3: core 0.15, PP-006, Dk 4.1
Layer 3: signal copper 0.14
Dielectric 7: prepreg 0.0711, PP-006, Dk 4.1
Layer 4: signal copper 0.14
Dielectric 1: prepreg 0.15, PP-006, Dk 4.1
Layer 5: signal copper 0.14
Dielectric1: core 0.15, FR-4 High Tg, Dk 4.8
Layer 6: signal copper 0.14
Dielectric 2: prepreg 0.15, PP-006, Dk 4.1
Layer 7: signal copper 0.14
Dielectric 8: prepreg 0.0711, PP-006, Dk 4.1
Layer 8: signal copper 0.14
Dielectric 4: core 0.15, PP-006, Dk 4.1
Layer 9: signal copper 0.14
Dielectric 6: prepreg 0.15, PP-006, Dk 4.1
Bottom Layer: signal copper 0.07
Bottom Solder: solder mask 0.0102, Solder Resist, Dk 3.5

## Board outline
7,-16.999 7,0 -8.268,0.003 -8.263,67.94 101.746,67.935 101.745,0.013 86.499,-0.022 86.488,-16.978 71.535,-16.978 71.527,-0.05 21.996,-0.012 21.995,-16.999

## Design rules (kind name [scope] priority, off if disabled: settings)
AcuteAngle [All] p1: minimum=4.50000000000000E+0001 checktracksonly=FALSE
AssemblyTestPointUsage [All] p1: valid=2
Clearance Clearance-SurfaceLayer [OnTopLayer OR OnBottomLayer] p1: gap=0.2 ignorepadtopadclearanceinfootprint=FALSE
Clearance Clearance_BoardEdge_MountingHoles [OnCopper and InComponentClass('Mounting Holes') vs IsKeepOut] p2: gap=1.016 ignorepadtopadclearanceinfootprint=FALSE except(0: Arc-Hole Track-Hole SMDPad-Hole THPad-Hole Via-Hole Fill-Hole Poly-Hole Region-Hole Text-Hole)
Clearance Clearance_BoardEdge_Poly [OnCopper and InPoly vs IsKeepOut] p3: gap=0.25 ignorepadtopadclearanceinfootprint=FALSE except(0: Arc-Hole Track-Hole SMDPad-Hole THPad-Hole Via-Hole Fill-Hole Poly-Hole Region-Hole Text-Hole)
Clearance Clearance_BoardEdge [OnCopper and Not InComponentClass('Logo') and not InComponentClass('FiducialMark') and not InRegion(1000,500,4000,800) and Not IsKeepout vs IsKeepOut] p4: gap=0.127 ignorepadtopadclearanceinfootprint=FALSE except(0: Arc-Hole Track-Hole SMDPad-Hole THPad-Hole Via-Hole Fill-Hole Poly-Hole Region-Hole Text-Hole)
Clearance Clearance-InnerLayer [All] p5: gap=0.3 ignorepadtopadclearanceinfootprint=FALSE
Clearance Clearance_Poly [InPolygon] p6: gap=0.254 ignorepadtopadclearanceinfootprint=FALSE except(0: Arc-Hole Track-Hole SMDPad-Hole THPad-Hole Via-Hole Fill-Hole Poly-Hole Region-Hole Text-Hole)
ComponentClearance ComponentClearance_Logo [All] p1: gap=0.254 collisioncheckmode=3 verticalgap=0.254 showdistances=TRUE
ComponentClearance ComponentClearance_ScrewToNut [(HasFootprint('NY PMS 440 0025 PH')) vs (HasFootprint('Keystone_1902C'))] p2: gap=0.127 collisioncheckmode=3 verticalgap=0.254 showdistances=FALSE
ComponentClearance ComponentClearance_MountingHoles [InComponentClass('Mounting Holes')] p3: gap=0.254 collisioncheckmode=3 verticalgap=2540 showdistances=FALSE
ComponentClearance ComponentClearance_SmallPassives [HasFootprint('0201*') or HasFootprint('0402*') or HasFootprint('0508') or HasFootprint('0603*') or HasFootprint('0612') or HasFootprint('0805*') or HasFootprint('0815*') or HasFootprint('0830*') or HasFootprint('1206*') or HasFootprint('1210*') or HasFootprint('1808*') or HasFootprint('1812*') or HasFootprint('1825*') or HasFootprint('2010*') or HasFootprint('2220*') or HasFootprint('2225*') or HasFootprint('2512*') or HasFootprint('2728*') or HasFootprint('3518*') vs HasFootprint('0201*') or HasFootprint('0402*') or HasFootprint('0508') or HasFootprint('0603*') or HasFootprint('0612') or HasFootprint('0805*') or HasFootprint('0815*') or HasFootprint('0830*') or HasFootprint('1206*') or HasFootprint('1210*') or HasFootprint('1808*') or HasFootprint('1812*') or HasFootprint('1825*') or HasFootprint('2010*') or HasFootprint('2220*') or HasFootprint('2225*') or HasFootprint('2512*') or HasFootprint('2728*') or HasFootprint('3518*')] p4: gap=0.254 collisioncheckmode=3 verticalgap=0.254 showdistances=FALSE
ComponentClearance ComponentClearance_THtoSMT [IsThruComponent vs IsSMTComponent] p5: gap=0.254 collisioncheckmode=3 verticalgap=2540 showdistances=FALSE
ComponentClearance ComponentClearance_THtoTH [IsThruComponent vs IsThruComponent] p6: gap=0.254 collisioncheckmode=3 verticalgap=2540 showdistances=FALSE
ComponentClearance [All] p7: gap=0.254 collisioncheckmode=3 verticalgap=0.254 showdistances=FALSE
DiffPairsRouting [All] p1: maxlimit=2.54 minlimit=0.254 mostfreqgap=0.254 toplayer_minwidth=0.381 toplayer_maxwidth=0.381 toplayer_prefwidth=0.381 midlayer1_minwidth=0.381 midlayer1_maxwidth=0.381 midlayer1_prefwidth=0.381 midlayer2_minwidth=0.381 midlayer2_maxwidth=0.381 midlayer2_prefwidth=0.381 midlayer3_minwidth=0.381 midlayer3_maxwidth=0.381 midlayer3_prefwidth=0.381 midlayer4_minwidth=0.381 midlayer4_maxwidth=0.381 midlayer4_prefwidth=0.381 midlayer5_minwidth=0.381 midlayer5_maxwidth=0.381 midlayer5_prefwidth=0.381 midlayer6_minwidth=0.381 midlayer6_maxwidth=0.381 midlayer6_prefwidth=0.381 midlayer7_minwidth=0.381 midlayer7_maxwidth=0.381 midlayer7_prefwidth=0.381 midlayer8_minwidth=0.381 midlayer8_maxwidth=0.381 midlayer8_prefwidth=0.381 bottomlayer_minwidth=0.381 bottomlayer_maxwidth=0.381 bottomlayer_prefwidth=0.381 maxuncoupledlength=25.4
FabricationTestPointUsage TestPointUsage [All] p1: valid=2 allowmultiple=FALSE
FabricationTestpoint Testpoint [All] p1: side=3 testpointundercomponent=TRUE minsize=1.016 maxsize=2.54 preferedsize=1.524 minholesize=0 maxholesize=1.016 preferedholesize=0.813 testpointgrid=0.025 allowsidetop=TRUE allowsidebottom=TRUE usegrid=TRUE gridtolerance=0
FanoutControl Fanout_LCC [IsLCC] p1: bgadir=Out bgaviamode=Centered fanoutstyle=Auto fanoutdirection=Alternating viagrid=0.025 // Fanout_LCC (Default Rule)
FanoutControl Fanout_BGA [IsBGA] p2: bgadir=Out bgaviamode=Centered fanoutstyle=Auto fanoutdirection=Alternating viagrid=0.025 // Fanout_BGA (Default Rule)
FanoutControl Fanout_Default [All] p4: bgadir=Out bgaviamode=Centered fanoutstyle=Auto fanoutdirection=Alternating viagrid=0.025 // Fanout_Default (Default Rule)
FanoutControl Fanout_Small [(CompPinCount < 5)] p5: bgadir=Out bgaviamode=Centered fanoutstyle=Auto fanoutdirection=OutThenIn viagrid=0.025 // Fanout_Small (Default Rule)
HoleSize [All] p1: absolutevalues=TRUE maxlimit=6.375 minlimit=0.152 maxpercent=80.000 minpercent=20.000
MinimumAnnularRing [All] p1: minimumring=0.076
MinimumSolderMaskSliver MinimumSolderMaskSliver_Logo [InComponentClass('Logo') vs InComponentClass('Logo')] p1: minsoldermaskwidth=0.018
MinimumSolderMaskSliver [All] p2: minsoldermaskwidth=0
PlaneConnect [All] p1: planeconnectstyle=Direct reliefexpansion=0.254 reliefentries=4 reliefconductorwidth=0.254 reliefairgap=0.254
PolygonConnect [All] p1: connectstyle=Direct reliefconductorwidth=0.254 reliefentries=4 polygonreliefangle="90 Angle" airgapwidth=0.254
RoutingCorners [All] p1: cornerstyle=45-Degree minsetback=0.254 maxsetback=2.54
RoutingVias [All] p1: holewidth=0.406 width=0.864 viastyle="Through Hole" minholewidth=0.2 minwidth=0.406 maxholewidth=1.016 maxwidth=1.651
SMDToCorner [All] p1: distance=0
SilkToBoardRegionClearance [Not ((IsComment or IsDesignator) And (Hide <> 'False')) and not InRegion(1000,500,4000,800)] p1:
SilkToSilkClearance [All] p1: silktosilkclearance=0
SilkToSolderMaskClearance SilkscreenOverComponentPads [IsPad] p1: minsilkscreentomaskgap=0 clearancetoexposedcopper=TRUE
SolderMaskExpansion [All] p1: expansion=0.076 istentingtop=FALSE
Width [All] p1: maxlimit=2.54 minlimit=0.2 preferedwidth=0.3 toplayer_prefwidth=0.254 midlayer1_minwidth=0.3 midlayer2_minwidth=0.3 midlayer3_minwidth=0.3 midlayer4_minwidth=0.3 midlayer5_minwidth=0.3 midlayer6_minwidth=0.3 midlayer7_minwidth=0.3 midlayer8_minwidth=0.3 bottomlayer_prefwidth=0.254 minimp=50.000000 maximp=50.000000 favimp=50.000000 checkconnectedcopper=TRUE
14 further rules are at their usual default settings.

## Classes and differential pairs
component class Label: LBL1
component class "SR Card_Hardware": "CAUTION HOT SURFACE1" J1 LBL1 Logo1 Logo2 Logo3
component class "Power Stage": C6 C9 C12 C13 C15 C19 C20 C21 C22 C23 C24 C25 C28 C30 C31 C32 C33 D3 D4 D5 D6 D7 D8 D9 D10 D11 D12 D13 D14 J2 J3 J4 Q1 Q2 Q3 Q4 Q5 Q6 Q7 Q8 Q9 Q10 Q11 Q12 Q13 Q14 R1 R2 R3 R4 R9 R10 R11 R14 R15 R16 R17 R19 R20 R22 R23 R25 R26 R27 R28 R29 R30 R31 R32 R33 R34 R35 R36 R39 R40 R41 R42 R44 R45 R46 R47 R50 R54 R56 R57 R58 R59 R60 R61 R62 R63 R64 R65 R66 R67 R68 R70 R71 RT1 RT2 U4
component class Driver: C1 C2 C3 C4 C5 C7 C8 C10 C11 C14 C16 C17 C18 C26 C27 C29 C34 C35 C36 C37 D1 D2 D15 D16 D17 D18 D19 D20 R5 R6 R7 R8 R12 R13 R18 R21 R24 R37 R38 R43 R48 R49 R51 R52 R53 R55 R69 R80 R81 R82 R83 U1 U2 U3 U5 U6 U7 U8

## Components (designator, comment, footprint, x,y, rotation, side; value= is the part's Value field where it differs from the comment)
C1 "GCM155R71H104KE02D" 0402 -3.302,49.334 r270 bottom value=0.1uF
C2 "CGA3E1X7R1E105M080AC" 0603 6.007,62.832 r180 top value=1uF
C3 "CGA3E1X7R1E105M080AC" 0603 5.979,54.33 r180 bottom value=1uF
C4 "CC0402KRX7R9BB101" 0402 -6.389,48.709 r0 bottom value=100pF
C5 "CC0402KRX7R9BB101" 0402 0.397,56.67 r180 bottom value=100pF
C6 "GCM21BR72A104KA37L" 0805_HV 2.404,52.287 r180 top value=0.1uF
C7 "GRT155C71A105KE13D" 0402 -3.345,30.312 r180 top value=1uF
C8 "CGA3E1X7R1E105M080AC" 0603 4.544,28.125 r90 top value=1uF
C9 "GCM21BR72A104KA37L" 0805_HV 2.404,50.231 r180 top value=0.1uF
C10 "GCM155R71H104KE02D" 0402 -6.388,49.916 r180 bottom value=0.1uF
C11 "GCM155R71H104KE02D" 0402 -7.217,15.323 r90 bottom value=0.1uF
C12 "GRT155C71A105KE13D" 0402 1.351,39.795 r0 bottom value=1uF
C13 "GRT155C71A105KE13D" 0402 2.954,37.568 r90 bottom value=1uF
C14 "GCM155R71H104KE02D" 0402 -0.341,17.996 r0 bottom value=0.1uF
C15 "CGA2B3X7R1H103K050BB" 0402 0.484,35.601 r180 bottom value=0.01uF
C16 "CGA3E1X7R1E105M080AC" 0603 6.737,2.335 r0 top value=1uF
C17 "CC0402KRX7R9BB101" 0402 -4.2,15.782 r180 bottom value=100pF
C18 "CGA3E1X7R1E105M080AC" 0603 5.948,10.739 r180 bottom value=1uF
C19 "CGA2B2X7R1H332K050BA" 0402 10.007,37.295 r270 bottom value=3300pF
C20 "GCM21BR72A104KA37L" 0805_HV 2.404,54.343 r180 top value=0.1uF
C21 "GCM21BR72A104KA37L" 0805_HV 2.386,15.898 r180 top value=0.1uF
C22 "GCM21BR72A104KA37L" 0805_HV 2.404,46.12 r180 top value=0.1uF
C23 "GCM21BR72A104KA37L" 0805_HV 2.404,48.175 r180 top value=0.1uF
C24 "GCM21BR72A104KA37L" 0805_HV 2.386,20.055 r180 top value=0.1uF
C25 "GCM21BR72A104KA37L" 0805_HV 2.386,22.134 r180 top value=0.1uF
C26 "CGA3E1X7R1E105M080AC" 0603 3.621,40.661 r180 top value=1uF
C27 "CC0402KRX7R9BB101" 0402 2.379,10.868 r0 bottom value=100pF
C28 "CGA2B2X7R1H332K050BA" 0402 9.945,15.42 r270 bottom value=3300pF
C29 "GCM155R71H104KE02D" 0402 -5.243,56.763 r180 top value=0.1uF
C30 "GCM155R71H104KE02D" 0402 8.707,37.281 r270 bottom value=0.1uF
C31 "GCM155R71H104KE02D" 0402 8.61,15.423 r270 bottom value=0.1uF
C32 "GCM21BR72A104KA37L" 0805_HV 2.386,24.212 r180 top value=0.1uF
C33 "GCM21BR72A104KA37L" 0805_HV 2.386,17.977 r180 top value=0.1uF
C34 "GCM155R71H104KE02D" 0402 -2.679,34.727 r90 top value=0.1uF
C35 "CC0402KRX7R9BB101" 0402 -2.704,37.213 r270 top value=100pF
C36 "CC0402KRX7R9BB101" 0402 -0.635,40.614 r0 top value=100pF
C37 "GCM155R71H104KE02D" 0402 -5.387,25.028 r180 bottom value=0.1uF
"CAUTION HOT SURFACE1" "CAUTION HOT SURFACE" IEC_HotSurface_Small 75.301,61.365 r0 top
D1 "1N4148WQ-7-F" SOD-123 3.382,42.663 r180 top value=100V
D2 "1N4148WQ-7-F" SOD-123 1.106,27.178 r180 top value=100V
D3 "RB521S30T1G" SOD-523 71.203,64.154 r270 bottom value=30V
D4 "RB521S30T1G" SOD-523 71.249,31.648 r270 bottom value=30V
D5 "RB521S30T1G" SOD-523 71.281,51.535 r90 bottom value=30V
D6 "RB521S30T1G" SOD-523 71.124,9.844 r270 bottom value=30V
D7 "RB521S30T1G" SOD-523 71.2,55.013 r270 bottom value=30V
D8 "RB521S30T1G" SOD-523 71.141,20.754 r270 bottom value=30V
D9 "RB521S30T1G" SOD-523 9.784,42.66 r270 bottom value=30V
D10 "RB521S30T1G" SOD-523 9.767,9.959 r270 bottom value=30V
D11 "RB521S30T1G" SOD-523 9.753,53.53 r270 bottom value=30V
D12 "RB521S30T1G" SOD-523 9.756,21.052 r270 bottom value=30V
D13 "RB521S30T1G" SOD-523 9.72,64.334 r270 bottom value=30V
D14 "RB521S30T1G" SOD-523 9.765,31.874 r270 bottom value=30V
D15 "SS2PH10HM3_A/H" DO-220AA 6.248,59.834 r180 top value=100V
D16 "SZMM3Z15VST1G" SOD-323 8.512,64.386 r90 top value=15V
D17 "SS2PH10HM3_A/H" DO-220AA 4.699,8.876 r90 top value=100V
D18 "SZMM3Z15VST1G" SOD-323 6.518,4.634 r0 top value=15V
D19 "EDZVFHT2R4.7B" SOD-523 -5.213,58.344 r180 top value=4.7V
D20 "EDZVFHT2R4.7B" SOD-523 -5.387,26.382 r180 bottom value=4.7V
J1 "FTSH-107-01-L-D-RA" Samtec_FTSH-107-01-L-D-RA -0.701,4.561 r0 top
J2 "575-4" Keystone_575-4 79,-10 r0 top
J3 "575-4" Keystone_575-4 14.5,-10 r0 top
J4 "FTSH-102-01-L-D-RA" FP-FTSH-102-01-L-D-RA_HDR4-MFG 95.737,1.366 r180 top
LBL1 "THT-14-423-10" Label_650x200 60.248,61.833 r180 top
Logo1 "CE Mark" CE_Mark_5mm 15.103,61.098 r0 top
Logo2 "FCC disclaimer" FCC_disclaimer 43.321,56.668 r0 top
Logo3 "WEEE logo" WEEE_Minimum 22.422,61.29 r0 top
Q1 "IAUTN06S5N008T" SOIC120P1500X235-16N-1-V 60.17,61.08 r0 bottom
Q2 "IAUTN06S5N008T" SOIC120P1500X235-16N-1-V 60.17,39.471 r0 bottom
Q3 "IAUTN06S5N008T" SOIC120P1500X235-16N-1-V 60.17,50.404 r0 bottom
Q4 "IAUTN06S5N008T" SOIC120P1500X235-16N-1-V 60.17,17.674 r0 bottom
Q5 "IAUTN06S5N008T" SOIC120P1500X235-16N-1-V 60.17,6.793 r0 bottom
Q6 "IAUTN06S5N008T" SOIC120P1500X235-16N-1-V 60.17,28.534 r0 bottom
Q7 "IAUTN06S5N008T" SOIC120P1500X235-16N-1-V 22.141,39.471 r0 bottom
Q8 "IAUTN06S5N008T" SOIC120P1500X235-16N-1-V 22.163,50.388 r0 bottom
Q9 "IAUTN06S5N008T" SOIC120P1500X235-16N-1-V 22.133,61.11 r0 bottom
Q10 "IAUTN06S5N008T" SOIC120P1500X235-16N-1-V 22.141,28.534 r0 bottom
Q11 "IAUTN06S5N008T" SOIC120P1500X235-16N-1-V 22.141,17.674 r0 bottom
Q12 "IAUTN06S5N008T" SOIC120P1500X235-16N-1-V 22.141,6.793 r0 bottom
Q13 "NVMFS5C604NLT1G" TRANS_DFN5 8.013,50.185 r180 top value=60V
Q14 "NVMFS5C604NLT1G" TRANS_DFN5 8.007,20.266 r180 top value=60V
R1 "CRCW04020000Z0EDHP" 0402 70.563,66.259 r180 bottom value=0
R2 "CRCW04020000Z0EDHP" 0402 70.616,33.852 r0 bottom value=0
R3 "RMCF0402FT10K0" 0402 9.373,39.454 r180 top value=10.0k
R4 "RMCF0402FT10K0" 0402 10.004,29.885 r0 top value=10.0k
R5 "CRCW08054R70FKEAHP" 0805_HV 2.748,58.384 r270 top value=4.70
R6 "RL0510S-2R2-F" 0402 -1.333,50.024 r0 bottom value=2.20
R7 "CRCW08054R70FKEAHP" 0805_HV -0.87,42.426 r180 top value=4.70
R8 "RL0510S-2R2-F" 0402 -2.114,29.093 r0 top value=2.20
R9 "CRCW04020000Z0EDHP" 0402 70.631,49.34 r180 bottom value=0
R10 "CRCW04020000Z0EDHP" 0402 70.485,12.006 r0 bottom value=0
R11 "ERJPA2F1002X" 0402 73.139,55.586 r180 bottom value=10.0k
R12 "RMCF0402JT10R0" 0402 0.397,55.528 r0 bottom value=10.0
R13 "CRCW0402100RFKED" 0402 -7.087,46.663 r90 bottom value=100
R14 "ERJPA2F1002X" 0402 71.749,24.14 r0 bottom value=10.0k
R15 "CRCW04020000Z0EDHP" 0402 70.565,57.211 r180 bottom value=0
R16 "CRCW04020000Z0EDHP" 0402 70.5,22.969 r0 bottom value=0
R17 "CRCW08050000Z0EA" 0805_HV -1.356,46.12 r0 top value=0
R18 "CRCW06032R00JNEA" 0603 7.291,37.943 r0 top value=2.0
R19 "CRCW08050000Z0EA" 0805_HV -1.356,50.231 r0 top value=0
R20 "CRCW08050000Z0EA" 0805_HV -1.356,52.287 r0 top value=0
R21 "CRCW08054R70FKEAHP" 0805_HV -3.077,27.234 r0 top value=4.70
R22 "RMCF0402FT10K0" 0402 9.276,39.256 r180 bottom value=10.0k
R23 "CRCW08050000Z0EA" 0805_HV -1.356,48.175 r0 top value=0
R24 "CRCW0402100RFKED" 0402 -7.229,12.743 r90 bottom value=100
R25 "CRCW08050000Z0EA" 0805_HV -1.385,24.212 r0 top value=0
R26 "CRCW04020000Z0EDHP" 0402 11.756,10.992 r180 bottom value=0
R27 "CRCW08050000Z0EA" 0805_HV -1.385,22.134 r0 top value=0
R28 "CRCW08050000Z0EA" 0805_HV -1.385,20.055 r0 top value=0
R29 "LR12FTDR0M50" 2512 75.459,8.855 r270 bottom value=0.0005
R30 "CRCW04020000Z0EDHP" 0402 11.737,43.685 r0 bottom value=0
R31 "CRCW08050000Z0EA" 0805_HV -1.387,17.977 r0 top value=0
R32 "CRCW08050000Z0EA" 0805_HV -1.356,54.343 r0 top value=0
R33 "CRCW04020000Z0EDHP" 0402 11.764,21.884 r180 bottom value=0
R34 "CRCW08050000Z0EA" 0805_HV -1.405,15.898 r0 top value=0
R35 "CRCW04020000Z0EDHP" 0402 69.888,64.322 r90 bottom value=0
R36 "CRCW04020000Z0EDHP" 0402 11.75,54.609 r0 bottom value=0
R37 "CRCW06032R00JNEA" 0603 7.232,31.566 r0 top value=2.0
R38 "RL0510S-2R2-F" 0402 -0.341,16.881 r0 bottom value=2.20
R39 "CRCW04020000Z0EDHP" 0402 11.746,32.764 r180 bottom value=0
R40 "LR12FTDR0M50" 2512 79.175,8.855 r270 bottom value=0.0005
R41 "LR12FTDR0M50" 2512 82.892,8.855 r270 bottom value=0.0005
R42 "CRCW04020000Z0EDHP" 0402 11.693,65.365 r0 bottom value=0
R43 "CRCW0402100RFKED" 0402 -3.946,33.319 r90 top value=100
R44 "RMCF0402FT10K0" 0402 9.181,17.335 r180 bottom value=10.0k
R45 "ERJPA2F1002X" 0402 10.319,44.858 r180 bottom value=10.0k
R46 "LR12FTDR0M50" 2512 86.608,8.855 r270 bottom value=0.0005
R47 "LR12FTDR0M50" 2512 90.324,8.855 r270 bottom value=0.0005
R48 "RMCF0402JT10R0" 0402 -5.715,46.702 r90 bottom value=10.0
R49 "RMCF0402JT10R0" 0402 -4.726,14.355 r180 bottom value=10.0
R50 "LR12FTDR0M50" 2512 90.324,8.855 r270 top value=0.0005
R51 "ERJPA2F1002X" 0402 -2.679,32.236 r270 top value=10.0k
R52 "RMCF0402JT10R0" 0402 -3.263,40.624 r0 top value=10.0
R53 "RMCF0402JT10R0" 0402 1.657,8.877 r90 bottom value=10.0
R54 "ERJPA2F1002X" 0402 9.755,23.998 r90 bottom value=10.0k
R55 "RMCF0402JT10R0" 0402 -3.938,37.226 r90 top value=10.0
R56 "LR12FTDR0M50" 2512 86.62,8.845 r270 top value=0.0005
R57 "LR12FTDR0M50" 2512 82.867,8.855 r270 top value=0.0005
R58 "LR12FTDR0M50" 2512 79.179,8.845 r270 top value=0.0005
R59 "LR12FTDR0M50" 2512 75.458,8.834 r270 top value=0.0005
R60 "CRCW04020000Z0EDHP" 0402 69.926,31.769 r270 bottom value=0
R61 "CRCW04020000Z0EDHP" 0402 69.807,20.88 r270 bottom value=0
R62 "CRCW04020000Z0EDHP" 0402 69.866,55.176 r90 bottom value=0
R63 "CRCW04020000Z0EDHP" 0402 69.948,51.289 r270 bottom value=0
R64 "CRCW04020000Z0EDHP" 0402 11.726,42.031 r0 bottom value=0
R65 "CRCW04020000Z0EDHP" 0402 11.756,9.409 r180 bottom value=0
R66 "CRCW04020000Z0EDHP" 0402 69.781,9.967 r270 bottom value=0
R67 "CRCW04020000Z0EDHP" 0402 11.742,52.935 r0 bottom value=0
R68 "CRCW04020000Z0EDHP" 0402 11.766,20.512 r180 bottom value=0
R69 "CRCW08054R70FKEAHP" 0805_HV 2.205,10.946 r90 top value=4.70
R70 "CRCW04020000Z0EDHP" 0402 11.697,63.667 r0 bottom value=0
R71 "CRCW04020000Z0EDHP" 0402 11.762,31.26 r180 bottom value=0
R80 "ERA-2APB102X" 0402 -1.562,57.057 r0 top value=1.00k
R81 "ERA-2APB102X" 0402 -1.57,58.108 r0 top value=1.00k
R82 "ERA-2APB102X" 0402 -6.011,28.455 r90 bottom value=1.00k
R83 "ERA-2APB102X" 0402 -4.788,28.455 r90 bottom value=1.00k
RT1 "TMP6131QDECRQ1" DEC0002A-MFG 11.278,15.141 r90 bottom
RT2 "TMP6131QDECRQ1" DEC0002A-MFG 11.407,37.469 r90 bottom
U1 "UCC27332QDGNRQ1" DGN0008G-MFG 4.797,64.456 r0 bottom
U2 "ISO7720FQDRQ1" D0008A_N -5.211,54.419 r90 bottom
U3 "UCC27332QDGNRQ1" DGN0008G-MFG 4.731,57.178 r0 bottom
U4 "TPS71733QDRVRQ1" DRV0006A 0.785,37.609 r90 bottom
U5 "UCC21222QDRQ1" D0016B-MFG 1.606,34.749 r0 top
U6 "UCC27332QDGNRQ1" DGN0008G-MFG 6.509,5.671 r270 bottom
U7 "ISO7720FQDRQ1" D0008A_N -5.313,20.099 r90 bottom
U8 "UCC27332QDGNRQ1" DGN0008G-MFG 4.536,13.451 r0 bottom

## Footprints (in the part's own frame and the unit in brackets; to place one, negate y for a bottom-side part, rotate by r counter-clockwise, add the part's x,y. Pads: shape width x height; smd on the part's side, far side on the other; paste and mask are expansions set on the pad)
0402 [mm] "0402 from SM-752 data"
  rect 0.8x0.6 smd: 1(-0.6,0) 2(0.6,0)
  silkscreen extent -1.22,-0.52 1.22,0.52, body extent -0.55,-0.3 0.55,0.3, height 0.6
0603 [mm] "0603 from SM-752 data"
  rect 1x0.95 smd: 1(-0.8,0) 2(0.8,0)
  silkscreen extent -1.52,-0.69 1.52,0.69, body extent -0.87,-0.47 0.87,0.47, height 1
0805_HV [mil] "0805 with 30mil clearance between pads"
  rect 50x63 smd: 1(-40,0) 2(40,0)
  silkscreen extent -74,-40 74,40, body extent -43,-29 43,29, height 57
2512 [mm] "Chip Resistor, Body 6.3x3.2mm, IPC Medium Density"
  rect 1.3x3.4 smd: 1(-2.95,0) 2(2.95,0)
  silkscreen extent -1.9,-1.6 1.9,1.6, body extent -3.22,-1.67 3.22,1.67, height 0.71
CE_Mark_5mm [mm] "Minimum text height for CE Mark"
  silkscreen extent -3.5,-2.5 3.5,2.5
D0008A_N [mm] "SOIC, 8-Leads, Body 4.9x3.9mm, Pitch 1.27mm, IPC Medium Density"
  oval 1.45x0.6 smd: 1(-2.725,1.905) 2(-2.725,0.635) 3(-2.725,-0.635) 4(-2.725,-1.905) 5(2.725,-1.905) 6(2.725,-0.635) 7(2.725,0.635) 8(2.725,1.905)
  silkscreen extent -3.3,-2.5 0.9,2.5, body extent -3,-2.45 3,2.45, height 1.63
D0016B-MFG [mm]
  rrect17% 1.55x0.6 smd paste-1000 mask+0: 1(-2.7,4.445) 2(-2.7,3.175) 3(-2.7,1.905) 4(-2.7,0.635) 5(-2.7,-0.635) 6(-2.7,-1.905) 7(-2.7,-3.175) 8(-2.7,-4.445) 9(2.7,-4.445) 10(2.7,-3.175) 11(2.7,-1.905) 12(2.7,-0.635) 13(2.7,0.635) 14(2.7,1.905) 15(2.7,3.175) 16(2.7,4.445)
  silkscreen extent -4.17,-5 1.55,5, body extent -3.57,-5.25 3.57,5.25, height 0.25
DEC0002A-MFG [mm]
  rrect40% 0.25x0.5 smd paste-1000 mask+0: 1(-0.325,0) 2(0.325,0)
  silkscreen extent -1.17,-0.65 0.53,0.65, body extent -0.5,-0.3 0.5,0.3, height 0.5
DGN0008G-MFG [mm]
  rrect22% 1.4x0.45 smd paste+0 mask+0: 1(-2.2,0.975) 2(-2.2,0.325) 3(-2.2,-0.325) 4(-2.2,-0.975) 5(2.2,-0.975) 6(2.2,-0.325) 7(2.2,0.325) 8(2.2,0.975)
  rrect5% 2x3 smd paste-1000 mask-1000: 9(0,0)
  silkscreen extent -3.62,-1.88 1.55,1.88, body extent -2.46,-1.5 2.46,1.5, height 1.1
DO-220AA [mm] "Vishay recommended land pattern 12-Mar-12"
  rect 2.67x2.54 smd: 1(-1.175,0)
  rect 0.762x1.27 smd: 2(1.175,0)
  silkscreen extent 0.49,-1.09 1.47,1.09, body extent -2.44,-1.15 1.49,1.15, height 1.17
DRV0006A [mm] "SON, 6-Leads, Body 2x2mm, Pitch 0.65mm, Thermal Pad 1.6x1mm, TI Recommended"
  rrect33% 0.45x0.3 smd: 1(-0.975,0.65) 2(-0.975,0) 3(-0.975,-0.65) 4(0.975,-0.65) 5(0.975,0) 6(0.975,0.65)
  rrect14% 1x0.7 on Bottom Paste: 7(0,-0.45) 7(0,0.45)
  rrect10% 1x1.6 smd paste-0.5: 7(0,0)
  silkscreen extent -1.05,-1.2 1.05,1.2, body extent -1.05,-1.05 1.05,1.05, height 0.81
FCC_disclaimer [mm]
FP-FTSH-102-01-L-D-RA_HDR4-MFG [mm]
  rrect9% 0.95x0.95 hole 0.7 paste-1000 mask+0: 1(0.635,-2.525)
  round 0.95 hole 0.7 paste-1000 mask+0: 2(0.635,-3.795) 3(-0.635,-2.525) 4(-0.635,-3.795)
  silkscreen extent -1.3,-2.65 1.87,1.32, body extent -1.4,-4.45 1.4,4.6, height 0.25
IEC_HotSurface_Small [mm]
  silkscreen extent -2.72,-2.36 2.72,2.35
Keystone_575-4 [mm] "Banana Jack"
  round 10 hole 5.45: 1(0,0)
  body extent -3.95,-3.95 3.92,3.93, height 2.36
Label_650x200 [mil] "Thermal Transfer Label"
  round 1 on Mech13: 0(0,0)
  silkscreen extent -325,-100 325,100, body extent -325,-100 325,100, height 1
Samtec_FTSH-107-01-L-D-RA [mm] "SAMTEC"
  rect 0.95x0.95 hole 0.65: 1(-3.81,-0.635)
  round 0.95 hole 0.65: 2(-3.81,0.635) 3(-2.54,-0.635) 4(-2.54,0.635) 5(-1.27,-0.635) 6(-1.27,0.635) 7(0,-0.635) 8(0,0.635) 9(1.27,-0.635) 10(1.27,0.635) 11(2.54,-0.635) 12(2.54,0.635) 13(3.81,-0.635) 14(3.81,0.635)
  silkscreen extent -4.8,-7.49 4.44,-1.27, body extent -4.44,-7.47 4.44,0.84, height 3.44
SOD-123 [mm] "On Semi recommended land pattern"
  rect 0.915x1.22 smd: 1(-1.637,0) 2(1.637,0)
  silkscreen extent -2.74,-1.17 2.03,1.17, body extent -1.93,-0.9 1.93,0.9, height 1.35
SOD-323 [mm] "NXP recommended land pattern"
  rect 0.6x0.6 smd paste-0.05: 1(-1.1,0) 2(1.1,0)
  silkscreen extent -2.06,-0.86 1.53,0.86, body extent -1.3,-0.67 1.3,0.68, height 1.1
SOD-523 [mm] "NXP Semiconductor recommended land pattern, nominal STEP model"
  rect 0.8x0.6 smd paste-0.05: 1(-0.55,0) 2(0.55,0)
  silkscreen extent -1.65,-0.66 1.2,0.66, body extent -0.8,-0.4 0.8,0.4, height 0.72
SOIC120P1500X235-16N-1-V [mm] "SOIC,1.20mm pitch;16 pin,10.15mm W X 9.90mm L X 2.35mm H body"
  rect 3.375x0.8 smd paste+0 mask+0: 1(-7.187,4.2) 2(-7.187,3) 3(-7.187,1.8) 4(-7.187,0.6) 5(-7.187,-0.6) 6(-7.187,-1.8) 7(-7.187,-3) 8(-7.187,-4.2) 9(7.187,-4.2) 10(7.187,-3) 11(7.187,-1.8) 12(7.187,-0.6) 13(7.187,0.6) 14(7.187,1.8) 15(7.187,3) 16(7.187,4.2)
  silkscreen extent -8.77,-5 5.1,5.28, body extent -7.5,-4.95 7.5,4.95, height 2.2
TRANS_DFN5 [mm] "OnSemi recommended land pattern Case 488AA Issue G dated 23 APR 2012"
  rect 1x0.75 smd mask+0.051: 1(-2.748,1.905) 2(-2.748,0.635) 3(-2.748,-0.635) 4(-2.748,-1.905) 5(2.748,-1.905) 6(2.748,1.905)
  Top Layer region: -0.858,2.775 0.047,2.775 0.047,-2.775 -0.858,-2.775
  Top Layer region: -1.282,2.28 2.773,2.28 2.773,-2.28 -1.282,-2.28
  silkscreen extent -3.21,-2.68 -1.35,2.93, body extent -3.05,-2.57 3.1,2.58, height 1.13
WEEE_Minimum [mm] "WEEElie bin"
  silkscreen extent -2.42,-4.38 2.52,2.65

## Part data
C1 C10 C11 C14 C29 C30 C31 C34 C37: library part CMP-0006356-1, "CAP, CERM, 0.1 uF, 50 V, +/- 10%, X7R, AEC-Q200 Grade 1, 0402", Cap_Case=0402, Manufacturer=MuRata, Supplier Part Number 1=490-10672-1-ND, TempCo=X7R, Tolerance_%=10%, Value1=Unknown, Value2=50V, ValueDisplayed=0.1uF
C2 C3 C8 C16 C18 C26: library part CMP-0082113-1, "CAP, CERM, 1 µF, 25 V,+/- 20%, X7R, AEC-Q200 Grade 1, 0603", Cap_Case=0603, Manufacturer=TDK, Supplier Part Number 1=445-12548-2-ND, TempCo=X7R, Tolerance_%=20%, Value2=25V, ValueDisplayed=1µF
C4 C5 C17 C27 C35 C36: library part CMP-0006305-2, "CAP, CERM, 100 pF, 50 V, +/- 10%, X7R, 0402", Cap_Case=0402, Manufacturer="Yageo America", Supplier Part Number 1=311-1419-1-ND, TempCo=X7R, Tolerance_%=10%, Value1=Unknown, Value2=50V, ValueDisplayed=100pF
C6 C9 C20 C21 C22 C23 C24 C25 C32 C33: library part CMP-0860440-1, "CAP, CERM, 0.1 µF, 100 V,+/- 10%, X7R, AEC-Q200 Grade 1, 0805", Cap_Case=0805, Manufacturer=MuRata, TempCo=X7R, Tolerance_%=10%, Value2=100V, ValueDisplayed=0.1µF
C7 C12 C13: library part CMP-0085818-1, "CAP, CERM, 1 µF, 10 V,+/- 10%, X7S, AEC-Q200 Grade 1, 0402", Cap_Case=0402, Manufacturer=MuRata, TempCo=X7S, Tolerance_%=10%, Value2=10V, ValueDisplayed=1µF
C15: library part CMP-0006324-2, "CAP, CERM, 0.01 uF, 50 V, +/- 10%, X7R, AEC-Q200 Grade 1, 0402", Cap_Case=0402, Manufacturer=TDK, Supplier Part Number 1=445-6893-1-ND, TempCo=X7R, Tolerance_%=10%, Value1="0.333065 ohm", Value2=50V, ValueDisplayed=0.01uF
C19 C28: library part CMP-0006319-2, "CAP, CERM, 3300 pF, 50 V, +/- 10%, X7R, AEC-Q200 Grade 1, 0402", Cap_Case=0402, Manufacturer=TDK, Supplier Part Number 1=445-6891-1-ND, TempCo=X7R, Tolerance_%=10%, Value1="0.785178 ohm", Value2=50V, ValueDisplayed=3300pF
"CAUTION HOT SURFACE1": library part CMP-0074837-1, "IEC 61010-1 Hot Surface Warning"
D1 D2: library part CMP-0750148-1, "Diode, Switching, 100 V, 0.3 A, AEC-Q101, SOD-123", Manufacturer="Diodes Inc.", Value1=0.3A, Value2=1.25V
D3 D4 D5 D6 D7 D8 D9 D10 D11 D12 D13 D14: library part CMP-0028768-3, "Diode, Schottky, 30 V, 0.2 A, AEC-Q101, SOD-523", Manufacturer="ON Semiconductor", Value1=0.2A, Value2=0.5V
D15 D17: library part CMP-0028941-1, "Diode, Schottky, 100 V, 2 A, AEC-Q101, DO-220AA", Manufacturer=Vishay-Semiconductor, Supplier Part Number 1=78-SS2PH10HM3_A/H, Value1=2A, Value2=0.77V
D16 D18: library part CMP-0085761-1, "Diode, Zener, 15 V, 300 mW, AEC-Q101, SOD-323", Manufacturer="ON Semiconductor", Power_W=300mW, Value1=0.3W
D19 D20: library part CMP-0005910-2, "Diode, Zener, 4.7 V, 150 mW, AEC-Q101, SOD-523", Manufacturer=Rohm, Power_W=150mW, Supplier Part Number 1=78Y8306, Value1=0.15W
J1: library part CMP-0056012-2, "Header, 50mil, 7x2, R/A, TH", Manufacturer=Samtec, Supplier Part Number 1=FTSH-107-01-L-D-RA-ND
J2 J3: library part CMP-0055165-2, "Standard Banana Jack, Uninsulated, 5.5mm", Manufacturer=Keystone, Supplier Part Number 1=36-575-4-ND
J4: library part CMP-0120912-1, "Connector Unshrouded Header HDR 4 POS 1.27mm Solder RA Thru-Hole", Current_A=3.4A, Digikey Part Number=612-FTSH-102-01-L-D-RA-ND, Manufacturer=Samtec, Mouser Part Number=200-FTSH10201LDRA, Operating Temperature Range="-55°C to +125°C"
LBL1: library part CMP-0003625-1, "Thermal Transfer Printable Labels, 0.650\" W x 0.200\" H - 10,000 per roll", Manufacturer=Brady, Supplier Part Number 1=97C5133
Logo1: library part CMP-0074844-1
Logo2: library part CMP-0074847-1, "FCC_disclaimer"
Logo3: library part CMP-0074769-1
Q1 Q2 Q3 Q4 Q5 Q6 Q7 Q8 Q9 Q10 Q11 Q12: "Insulated-Gate Field-Effect Transistor (IGFET), N-Channel, Enhancement, Body Diode, Pin 1 Source, 2 Source, 3 Source , 4 Source, 5 Source, 6 Source, 7 Source, 8 Gate, 9 Drain, 10 Drain, 11 Drain, 12 Drain, 13 Drain, 14 Drain, 15 Drain, 16 Drain, 16 Pins", Manufacturer="Infineon Technologies", Package Reference=PG-HDSOP-16-2
Q13 Q14: library part CMP-0077633-1, "MOSFET, N-CH, 60 V, 287 A, AEC-Q101, DFN5 5x6mm", Alternate Manufacturer=None, Manufacturer="ON Semiconductor", Supplier Part Number 1=NVMFS5C604NLT1G-ND, Value1="0.0017 ohm", Value2="52 nC"
R1 R2 R9 R10 R15 R16 R26 R30 R33 R35 R36 R39 R42 R60 R61 R62 R63 R64 R65 R66 R67 R68 R70 R71: library part CMP-0081856-1, "RES, 0, 0%, 0.2 W, AEC-Q200 Grade 0, 0402", Manufacturer=Vishay-Dale, Power_W=200mW, Supplier Part Number 1=541-0.0YBTR-ND, Tolerance_%=0%, Value2=0.2W, Value_Code=0
R3 R4 R22 R44: library part CMP-0026754-1, "RES, 10.0 k, 1%, 0.063 W, AEC-Q200 Grade 0, 0402", Manufacturer="Stackpole Electronics Inc", Power_W=63mW, Supplier Part Number 1=RMCF0402FT10K0CT-ND, TempCo="100 ppm/C", Tolerance_%=1%, Value2=0.063W, Value_Code=10k0, ValueDisplayed=10.0k
R5 R7 R21 R69: library part CMP-0021312-3, "RES, 4.70, 1%, 0.5 W, AEC-Q200 Grade 0, 0805", Manufacturer=Vishay-Dale, Power_W=500mW, Supplier Part Number 1=541-4.70TCT-ND, TempCo="100 ppm/C", Tolerance_%=1%, Value2=0.5W, Value_Code=4R70, ValueDisplayed=4.70
R6 R8 R38: library part CMP-0082064-1, "RES, 2.20, 1%, 0.167 W, AEC-Q200 Grade 0, 0402", Manufacturer="Susumu Co Ltd", Power_W=167mW, Supplier Part Number 1=RL05S2.2FCT-ND, TempCo="200 ppm/C", Tolerance_%=1%, Value2=0.167W, Value_Code=2R20, ValueDisplayed=2.20
R11 R14 R45 R51 R54: library part CMP-0078779-1, "RES, 10.0 k, 1%, 0.2 W, AEC-Q200 Grade 0, 0402", Manufacturer=Panasonic, Power_W=200mW, Supplier Part Number 1=P17230CT-ND, TempCo="100 ppm/C", Tolerance_%=1%, Value2=0.2W, Value_Code=10k0, ValueDisplayed=10.0k
R12 R48 R49 R52 R53 R55: library part CMP-0026764-1, "RES, 10.0, 1%, 0.063 W, AEC-Q200 Grade 0, 0402", Manufacturer="Stackpole Electronics Inc", Power_W=63mW, Supplier Part Number 1=RMCF0402JT10R0CT-ND, TempCo="100 ppm/C", Tolerance_%=1%, Value2=0.063W, Value_Code=10R0, ValueDisplayed=10.0
R13 R24 R43: library part CMP-0025951-3, "RES, 100, 1%, 0.063 W, AEC-Q200 Grade 0, 0402", Manufacturer=Vishay-Dale, Power_W=63mW, Supplier Part Number 1=541-100LCT-ND, TempCo="100 ppm/C", Tolerance_%=1%, Value2=0.063W, Value_Code=100R, ValueDisplayed=100
R17 R19 R20 R23 R25 R27 R28 R31 R32 R34: library part CMP-0020442-3, "RES, 0, 5%, 0.125 W, AEC-Q200 Grade 0, 0805", Manufacturer=Vishay-Dale, Power_W=125mW, Supplier Part Number 1=541-0.0ACT-ND, TempCo="200 ppm/C", Tolerance_%=5%, Value2=0.125W, Value_Code=0000, ValueDisplayed=0
R18 R37: library part CMP-0025776-4, "RES, 2.0, 5%, 0.1 W, AEC-Q200 Grade 0, 0603", Manufacturer=Vishay-Dale, Power_W=100mW, Supplier Part Number 1=541-2.0GCT-ND, TempCo="200 ppm/C", Tolerance_%=5%, Value2=0.1W, Value_Code=2R00, ValueDisplayed=2.0
R29 R40 R41 R46 R47 R50 R56 R57 R58 R59: library part CMP-0078924-1, "RES, 0.0005, 1%, 3 W, AEC-Q200 Grade 0, 2512", Power_W=1W, Supplier Part Number 1=89T4329, TempCo="75 ppm/C", Tolerance_%=1%, Value_Code=M50, ValueDisplayed=0.0005
R80 R81 R82 R83: library part CMP-0026790-1, "RES, 1.00 k, 0.1%, 0.063 W, AEC-Q200 Grade 0, 0402", Manufacturer=Panasonic, Power_W=63mW, Supplier Part Number 1=P1KCNCT-ND, TempCo="15 ppm/C", Tolerance_%=0.1%, Value2=0.063W, Value_Code=1k00, ValueDisplayed=1.00k
RT1 RT2: library part CMP-0120064-2, "Automotive ±1% tolerance 10kΩ linear thermistor available in an 0402 package option 2-X1SON -40 to 125", Digikey Part Number=296-53530-1-ND, Manufacturer="Texas Instruments", Mouser Part Number=595-TMP6131QDECRQ1, Operating Temperature Range="-40°C to +125°C"
U1 U3 U6 U8: library part CMP-0095529-1, "Single 9-A High Speed Low-Side MOSFET Driver W Enable", Manufacturer="Texas Instruments", Max Supply Voltage=18V, Min Supply Voltage=4V, Operating Temperature Range="-40°C to +125°C"
U2 U7: library part CMP-0860111-1, "Automotive, High Speed, Robust EMC Reinforced Dual-Channel Digital Isolator, D0008A (SOIC-8)", Alternate Manufacturer="Texas Instruments", Operating Temperature Range="-40 to 125 C", Rating=Automotive
U4: library part CMP-0082417-1, "Low Noise, High-Bandwidth PSRR Low-Dropout 150mA Linear Regulator for Automotive Applications, DRV0006A (WSON-6)", Alternate Manufacturer="Texas Instruments", Operating Temperature Range="-40 to 125 C", Rating=Automotive
U5: library part CMP-0090594-2, "Half-Bridge Gate Driver IC CMOS/TTL 16-SOIC", Digikey Part Number=296-UCC21222QDRQ1CT-ND, Manufacturer="Texas Instruments", Max Power Dissipation=1825mW, Max Supply Voltage=5.5V, Min Supply Voltage=3V, Mouser Part Number=595-UCC21222QDRQ1, Nominal Supply Current=1-2.5mA, Operating Temperature Range="-40°C to +125°C", Output Voltage=9.2-18V

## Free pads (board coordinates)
  round 5.6 hole 3.5: 1(-3.25,9.5) 1(-3.25,62.5) 1(96.75,62.5) 1(96.75,9.5)
  oval 6x5 hole 3.6: 4(36.5,25.55) 4(36.5,35) 4(36.5,44.45) 4(46.2,25.55) 4(46.2,35) 4(46.2,44.45)
  rrect30% 6.1x7.5 hole 4.1 square: 4(74.1,45)
  rrect50% 6.1x7.5 hole 4.1 square: 4(81,25)

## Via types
v1: diameter 0.8, hole 0.5, Top Layer to Bottom Layer, 1795 vias
v2: diameter 0.6, hole 0.3, Top Layer to Bottom Layer, 144 vias
v3: diameter 0.5, hole 0.2, Top Layer to Bottom Layer, 26 vias

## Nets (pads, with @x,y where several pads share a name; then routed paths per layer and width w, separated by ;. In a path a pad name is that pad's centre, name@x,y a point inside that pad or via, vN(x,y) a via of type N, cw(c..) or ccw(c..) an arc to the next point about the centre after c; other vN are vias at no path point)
3V3: C13.1 C30.1 C31.1 R6.2 R8.2 R22.2 R38.2 R44.2 U4.1 | length 67.4
  Top Layer w0.5: R8.2@-1.514,29.093 -0.053,29.093 1.113,30.26 v2(1.113,34.189)
  Bottom Layer w0.5: R6.2@-0.733,50.024 0,49.291 2.119,49.291 6.131,45.279 6.131,39.256 ; R38.2@0.259,16.881 8.502,16.881 8.61,16.99 ; v2(1.113,34.189) 1.99,34.189 2.954,35.153 C13.1@2.954,36.968 ; U4.1@1.435,36.634 2.028,36.634 2.362,36.968 C13.1@2.954,36.968 ; C31.1@8.61,16.023 8.61,16.99 ; C30.1@8.707,37.881 8.707,39.225 R22.2@8.676,39.256 6.131,39.256 ; C13.1@2.954,36.968 6.131,36.968 ; 6.131,36.968 6.131,39.256 ; 6.131,36.968 6.131,34.68 8.581,32.23 R44.2@8.581,17.335 8.61,17.306 8.61,16.99
5V0: C12.1 J1.4 U4.4 U4.6 | length 43.4
  Layer 2 w0.4: J1.4@-3.241,5.196 -3.241,5.305 -4.107,6.171 -5.434,6.171 -7.047,7.784 -7.047,33.392 -0.913,39.526 v2(0.647,39.526)
  Bottom Layer w0.3: U4.4@0.135,38.584 0.135,39.014 v2(0.647,39.526) 0.927,39.526 1.44,39.013 1.435,39.007 U4.6@1.435,38.584
12V: C3.1 C18.1 J1.3 R5.2 R7.2 R21.1 R69.2 U3.1 U3.8 U8.1 U8.8 | length 34.9
  Top Layer w0.6: v2(-2.594,42.607) -2.034,42.607 -2.03,42.604 R7.2@-1.727,42.604
  Layer 3 w0.6: v2(-2.594,42.607) 0.594,42.607 2.539,44.551 v2(2.539,55.953)
  Bottom Layer w0.6: v2(-3.476,26.277) -2.594,27.159 v2(-2.594,42.607)
  other v2: 6.812,11.432 1.614,11.838
"ACL PWM_1": J1.1 R52.1 | length 40.1
  Top Layer w0.254: J1.1@-4.511,3.926 -7.746,7.161 -7.746,37.48 -4.603,40.624 R52.1@-3.863,40.624
"ACL PWM_2": J1.2 R55.1 | length 34.2
  Top Layer w0.254: J1.2@-4.511,5.196 -7.026,7.711 -7.026,34.325 -4.725,36.626 R55.1@-3.938,36.626
ACL_G1: Q13.4 R3.2 R18.2 | length 15.7
  Top Layer w0.5: R18.2@8.091,37.943 8.773,38.625 R3.2@8.773,39.454 8.773,45.438 9.811,46.475 9.811,51.937 9.964,52.09 Q13.4@10.761,52.09
ACL_G2: Q14.4 R4.2 R37.2 | length 11.8
  Top Layer w0.5: R37.2@8.188,31.409 R37.2@8.032,31.566 9.857,31.566 10.754,30.668 10.754,30.047 Q14.4@10.754,22.171
AGND: C1.2 C4.1 C7.2 C10.2 C11.2 C12.2 C13.2 C14.2 C15.2 C17.1 C19.2 C28.2 C30.2 C31.2 C34.2 C35.2 C36.2 J1.5 J1.6 R51.2 RT1.1 RT2.1 U2.4 U4.3 U4.7@0.785,37.609 U5.4 U7.4 | length 21.2
  Top Layer w0.3: C7.2@-3.945,30.312 -3.945,30.891 -3.2,31.636 R51.2@-2.679,31.636
  Bottom Layer w0.254: C11.2@-7.217,15.923 U7.4@-7.217,17.374
  Bottom Layer w0.3: -4.187,47.999 -4.037,47.999 C1.2@-3.302,48.734 ; 7.617,15.428 8.222,14.823 C31.2@8.61,14.823 8.614,14.82 C28.2@9.945,14.82 RT1.1@11.175,14.82
  Bottom Layer w0.5: U7.4@-7.218,17.374 -7.218,18.399 -6.548,19.069 -0.207,19.069 0.259,18.603 C14.2@0.259,17.996 ; U2.4@-7.116,51.694 -7.116,50.044 -6.989,49.917 C4.1@-6.989,48.709
  other v2: -1.215,14.304 -4.201,30.963 7.669,35.112 -1.094,35.384 -4.422,39.157 -4.655,48.022 -7.149,50.622
  other v3: 0.21,37.606 0.785,37.609
DGND: C3.2 C5.2 C18.2 C27.2 J3.1 Q7.1 Q7.2 Q7.3 Q7.4 Q7.5 Q7.6 Q7.7 Q8.1 Q8.2 Q8.3 Q8.4 Q8.5 Q8.6 Q8.7 Q9.1 Q9.2 Q9.3 Q9.4 Q9.5 Q9.6 Q9.7 Q10.1 Q10.2 Q10.3 Q10.4 Q10.5 Q10.6 Q10.7 Q11.1 Q11.2 Q11.3 Q11.4 Q11.5 Q11.6 Q11.7 Q12.1 Q12.2 Q12.3 Q12.4 Q12.5 Q12.6 Q12.7 R17.1 R19.1 R20.1 R23.1 R25.1 R27.1 R28.1 R31.1 R32.1 R34.1 R45.1 R54.2 U3.4 U3.5 U3.9 U8.4 U8.5 U8.9
  other v1: 13.662,2.621 14.519,2.621 15.375,2.621 16.232,2.621 17.098,2.62 17.955,2.62 13.662,3.82 14.519,3.82 15.375,3.82 16.232,3.82 17.098,3.82 17.955,3.82 13.664,5.021 14.52,5.021 15.377,5.021 16.233,5.021 17.099,5.021 17.956,5.021 13.662,7.421 14.519,7.421 15.375,7.421 16.232,7.421 17.098,7.42 17.955,7.42 13.663,8.621 14.519,8.621 15.376,8.621 16.232,8.621 17.099,8.62 17.955,8.62 13.661,9.821 14.517,9.821 15.374,9.821 16.23,9.821 17.097,9.82 17.953,9.82 13.659,13.503 14.515,13.503 15.372,13.503 16.228,13.503 17.094,13.502 17.951,13.502 13.659,14.703 14.515,14.703 15.372,14.703 16.228,14.703 17.094,14.702 17.951,14.702 -2.174,15.405 13.66,15.904 14.516,15.904 15.373,15.904 16.229,15.904 17.096,15.903 17.952,15.903 -2.164,16.326 -2.164,17.254 13.659,18.303 14.515,18.303 15.372,18.303 16.228,18.303 17.094,18.303 17.951,18.303 13.659,19.503 14.516,19.503 15.372,19.503 16.229,19.503 17.095,19.503 17.951,19.503 -2.164,20.038 13.657,20.703 14.514,20.703 15.37,20.703 16.227,20.703 17.093,20.702 17.95,20.702 -2.164,20.966 -2.164,21.895 -2.164,22.823 -2.164,23.751 13.662,24.364 14.519,24.364 15.375,24.364 16.232,24.364 17.098,24.363 17.955,24.363 -2.164,24.679 13.662,25.564 14.519,25.564 15.375,25.564 16.232,25.564 17.098,25.563 17.955,25.563 13.664,26.765 14.52,26.765 15.377,26.765 16.233,26.765 17.099,26.764 17.956,26.764 13.662,29.164 14.519,29.164 15.375,29.164 16.232,29.164 17.098,29.163 17.955,29.163 13.663,30.364 14.519,30.364 15.376,30.364 16.232,30.364 17.099,30.363 17.955,30.363 13.661,31.564 14.517,31.564 15.374,31.564 16.23,31.564 17.097,31.563 17.953,31.563 13.659,35.3 14.515,35.3 15.372,35.3 16.228,35.3 17.095,35.299 17.951,35.299 13.659,36.499 14.515,36.499 15.372,36.499 16.228,36.499 17.095,36.498 17.951,36.498 13.66,37.7 14.517,37.7 15.373,37.7 16.23,37.7 17.096,37.7 17.953,37.7 13.659,40.1 14.515,40.1 15.372,40.1 16.228,40.1 17.095,40.099 17.951,40.099 13.66,41.3 14.516,41.3 15.373,41.3 16.229,41.3 17.095,41.299 17.952,41.299 13.658,42.499 14.514,42.499 15.371,42.499 16.227,42.499 17.093,42.499 17.95,42.499 13.661,46.233 14.517,46.233 15.374,46.233 16.23,46.233 17.096,46.233 17.953,46.233 -3.207,46.5 -2.151,46.535 13.661,47.433 14.517,47.433 15.374,47.433 16.23,47.433 17.096,47.432 17.953,47.432 -3.251,47.458 -2.151,47.463 -2.151,48.392 13.662,48.634 14.518,48.634 15.375,48.634 16.231,48.634 17.098,48.633 17.954,48.633 13.661,51.034 14.517,51.034 15.374,51.034 16.23,51.034 17.096,51.033 17.953,51.033 -2.151,51.176 -2.151,52.104 13.661,52.234 14.518,52.234 15.374,52.234 16.231,52.234 17.097,52.233 17.954,52.233 -3.192,53.032 -2.151,53.032 13.659,53.433 14.516,53.433 15.372,53.433 16.229,53.433 17.095,53.432 17.952,53.432 -3.192,53.961 -2.151,53.96 13.66,56.91 14.517,56.91 15.373,56.91 16.23,56.91 17.096,56.91 17.953,56.91 13.66,58.11 14.517,58.11 15.373,58.11 16.23,58.11 17.096,58.109 17.953,58.109 13.662,59.311 14.518,59.311 15.375,59.311 16.231,59.311 17.098,59.31 17.954,59.31 13.66,61.71 14.517,61.71 15.373,61.71 16.23,61.71 17.096,61.71 17.953,61.71 13.661,62.91 14.518,62.91 15.374,62.91 16.23,62.91 17.097,62.91 17.953,62.91 13.659,64.11 14.516,64.11 15.372,64.11 16.229,64.11 17.095,64.109 17.951,64.109
  other v2: 8.238,-3.832 9.71,-3.832 11.182,-3.832 12.654,-3.832 14.126,-3.832 15.598,-3.832 17.071,-3.832 18.543,-3.832 20.015,-3.832 8.236,-2.295 9.708,-2.295 11.18,-2.295 12.653,-2.295 14.125,-2.295 15.597,-2.295 17.069,-2.295 18.541,-2.295 20.014,-2.295 8.236,-0.75 9.708,-0.75 11.18,-0.75 12.653,-0.75 14.125,-0.75 15.597,-0.75 17.069,-0.75 18.541,-0.75 20.014,-0.75 59.824,2.548 60.758,2.529 -4.39,43.273 59.739,64.598 60.51,64.616 -6.99,66.167 -6.37,66.167 -6.99,66.817 -6.37,66.817
  other v3: 3.986,12.231 4.546,12.232 5.086,12.231 3.986,13.451 4.536,13.451 5.086,13.451 4.181,55.958 5.281,55.958 4.181,57.178 5.281,57.178 4.181,58.398 5.281,58.398
EN_ACL: J1.8 R43.1 | length 34.9
  Top Layer w0.254: v2(-4.171,31.96) -4.171,32.494 R43.1@-3.946,32.719
  Layer 8 w0.3: v2(-4.171,31.96) 0.648,31.96 2.911,29.698 2.911,18.136 2.473,17.698 2.473,8.408 -0.701,5.234 J1.8@-0.701,5.196
EN_SR: J1.7 R13.1 R24.1 | length 69.5
  Layer 5 w0.3: v2(-7.42,43.955) -7.42,42.569 -7.538,42.451 -7.538,2.926 -6.737,2.125 -1.288,2.125 -0.701,2.712 J1.7@-0.701,3.926
  Bottom Layer w0.254: v2(-7.42,43.955) -7.42,44.792 -7.075,45.137 -7.075,46.052 R13.1@-7.087,46.063 ; R24.1@-7.229,12.143 -7.229,12.043 -7.619,11.653 -7.619,3.433 -6.455,2.268 -1.349,2.268 -0.701,2.916 J1.7@-0.701,3.926
EN_SR1: C10.1 R13.2 U2.3 U3.3 | length 18.1
  Layer 3 w0.3: v2(-7.53,47.769) -5.893,49.407 v2(-5.893,50.607) -5.893,52.709 -0.868,57.734 v2(1.015,57.734)
  Bottom Layer w0.254: v2(1.015,57.734) 1.246,57.503 U3.3@2.531,57.503
  Bottom Layer w0.5: U2.3@-5.846,51.694 -5.846,50.654 v2(-5.893,50.607) -5.893,50.021 C10.1@-5.788,49.916
EN_SR2: C11.1 R24.2 U7.3 U8.3 | length 14.9
  Bottom Layer w0.254: U7.3@-5.948,17.374 -5.948,15.452 -6.676,14.723 C11.1@-7.217,14.723 -7.229,14.712 R24.2@-7.229,13.343 -6.525,13.343 -6.198,13.016 -0.044,13.016 0.715,13.776 U8.3@2.336,13.776
NetC1_1: C1.1 R6.1 U2.1 | length 3.2
  Bottom Layer w0.24: U2.1@-3.306,51.694 -3.306,49.938 C1.1@-3.302,49.934 -3.212,50.024 R6.1@-1.933,50.024
NetC2_1: C2.1 D15.1 D16.1 R80.2 R81.2 U1.1 U1.8
  other v2: 7.188,62.227
NetC4_2: C4.2 R48.2 U2.2 | length 5.4
  Bottom Layer w0.24: R48.2@-5.715,47.302 -5.715,48.635 C4.2@-5.789,48.709 -4.95,48.709 -4.576,49.083 U2.2@-4.576,51.694
NetC5_1: C5.1 R12.2 U3.2 | length 2.8
  Bottom Layer w0.254: R12.2@0.997,55.528 0.997,56.67 1.18,56.853 U3.2@2.531,56.853
NetC6_1: C6.1 C9.1 C20.1 C22.1 C23.1 Q13.5 Q13.6
  other v1: 5.037,49.327 6.042,49.327 7.048,49.327 5.062,51.205 6.068,51.205 7.073,51.205
NetC6_2: C6.2 C9.2 C20.2 C22.2 C23.2 R17.2 R19.2 R20.2 R23.2 R32.2
  other v2: -0.339,46.12 0.524,46.12 1.388,46.12 -0.34,48.284 0.524,48.284 1.388,48.284 0.524,50.34 1.388,50.34 -0.339,52.396 0.524,52.396 1.388,52.396 -0.34,54.476 0.524,54.476
NetC7_1: C7.1 R8.1 U5.3 U5.8 | length 11.4
  Top Layer w0.5: C7.1@-2.745,30.312 C7.1@-2.737,30.304 ; R8.1@-2.732,29.108 -2.732,30.3 C7.1@-2.737,30.304 ; U5.3@-1.094,36.654 0.013,36.654 0.217,36.451 0.217,30.85 -0.329,30.304 U5.8@-1.094,30.304 C7.1@-2.737,30.304
NetC8_1: C8.1 D2.1 U5.11 | length 8.7
  Top Layer w0.5: U5.11@4.306,32.844 3.276,32.844 2.601,32.169 2.601,27.283 4.29,27.283 C8.1@4.377,27.37
NetC14_1: C14.1 R38.1 U7.1 | length 4.3
  Bottom Layer w0.5: U7.1@-3.408,17.374 -3.408,17.693 -2.813,18.288 -1.233,18.288 C14.1@-0.941,17.996 R38.1@-0.941,16.881
NetC15_1: C15.1 U4.2 | length 1.2
  Bottom Layer w0.254: U4.2@0.785,36.634 0.785,35.9 C15.1@1.084,35.601
NetC16_1: C16.1 D17.1 D18.1 R82.2 R83.2 U6.1 U6.8 | length 48.7
  Top Layer w0.8: D17.1@5.412,6.602 5.412,2.96 C16.1@5.937,2.435
  Layer 5 w0.5: v2(-4.041,29.037) -3.592,28.588 6.165,28.588 9.692,25.061 9.692,3.63 8.374,2.311 6.143,2.311 5.316,3.138 v2(5.316,3.398)
  Bottom Layer w0.5: R82.2@-6.011,29.055 R83.2@-4.788,29.055 -4.77,29.037 v2(-4.041,29.037)
NetC17_2: C17.2 R49.2 U7.2 | length 3.3
  Bottom Layer w0.254: R49.2@-5.326,14.355 -5.326,15.256 C17.2@-4.8,15.782 -4.678,15.905 U7.2@-4.678,17.374
NetC21_1: C21.1 C24.1 C25.1 C32.1 C33.1 Q14.5 Q14.6
  other v1: 5.056,19.298 5.081,21.176 5.084,23.447 6.09,23.447 7.096,23.447
NetC21_2: C21.2 C24.2 C25.2 C32.2 C33.2 R25.2 R27.2 R28.2 R31.2 R34.2
  other v2: -0.369,20.055 0.507,20.055 1.37,20.055 -0.369,22.134 0.507,22.134 1.37,22.134 -0.369,24.212 0.507,24.212 1.37,24.212
NetC26_1: C26.1 D1.1 U5.16 | length 3.8
  Top Layer w0.5: U5.16@4.306,39.194 4.306,41.95 D1.1@5.02,42.663
NetC27_1: C27.1 R53.2 U8.2 | length 5.6
  Bottom Layer w0.254: R53.2@1.657,9.477 1.657,10.745 C27.1@1.779,10.868 1.16,10.868 0.987,11.04 0.987,12.854 1.259,13.126 U8.2@2.336,13.126
NetC29_1: C29.1 D19.1 R80.1 R81.1 U2.8
  other v2: -3.306,57.144
NetC34_1: C34.1 R43.2 U5.5 | length 2.9
  Top Layer w0.5: R43.2@-3.946,33.919 -3.738,34.127 C34.1@-2.679,34.127 -2.665,34.114 U5.5@-1.094,34.114
NetC35_1: C35.1 R55.2 U5.2 | length 2.9
  Top Layer w0.5: R55.2@-3.938,37.826 -3.925,37.813 C35.1@-2.704,37.813 -2.593,37.924 U5.2@-1.094,37.924
NetC36_1: C36.1 R52.2 U5.1 | length 2.9
  Top Layer w0.5: R52.2@-2.663,40.624 -1.244,40.624 C36.1@-1.235,40.614 -1.235,39.335 U5.1@-1.094,39.194
NetC37_1: C37.1 D20.1 R82.1 R83.1 U7.8 | length 6.9
  Bottom Layer w0.5: R82.1@-6.011,27.855 R83.1@-4.788,27.855 -4.837,27.805 D20.1@-4.837,26.382 -4.787,26.332 C37.1@-4.787,25.028 -3.408,23.649 U7.8@-3.408,22.824
  other v2: -3.672,23.916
